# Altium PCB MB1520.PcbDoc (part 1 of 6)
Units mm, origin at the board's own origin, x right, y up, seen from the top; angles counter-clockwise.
Board outline 159 x 88 mm, 6 copper layers (Top Layer, Signal Layer 1, Signal Layer 2, Signal Layer 3, Signal Layer 4, Bottom Layer), stack 1.572 mm thick; 473 components, 377 nets, 1832 pads, 1378 vias.
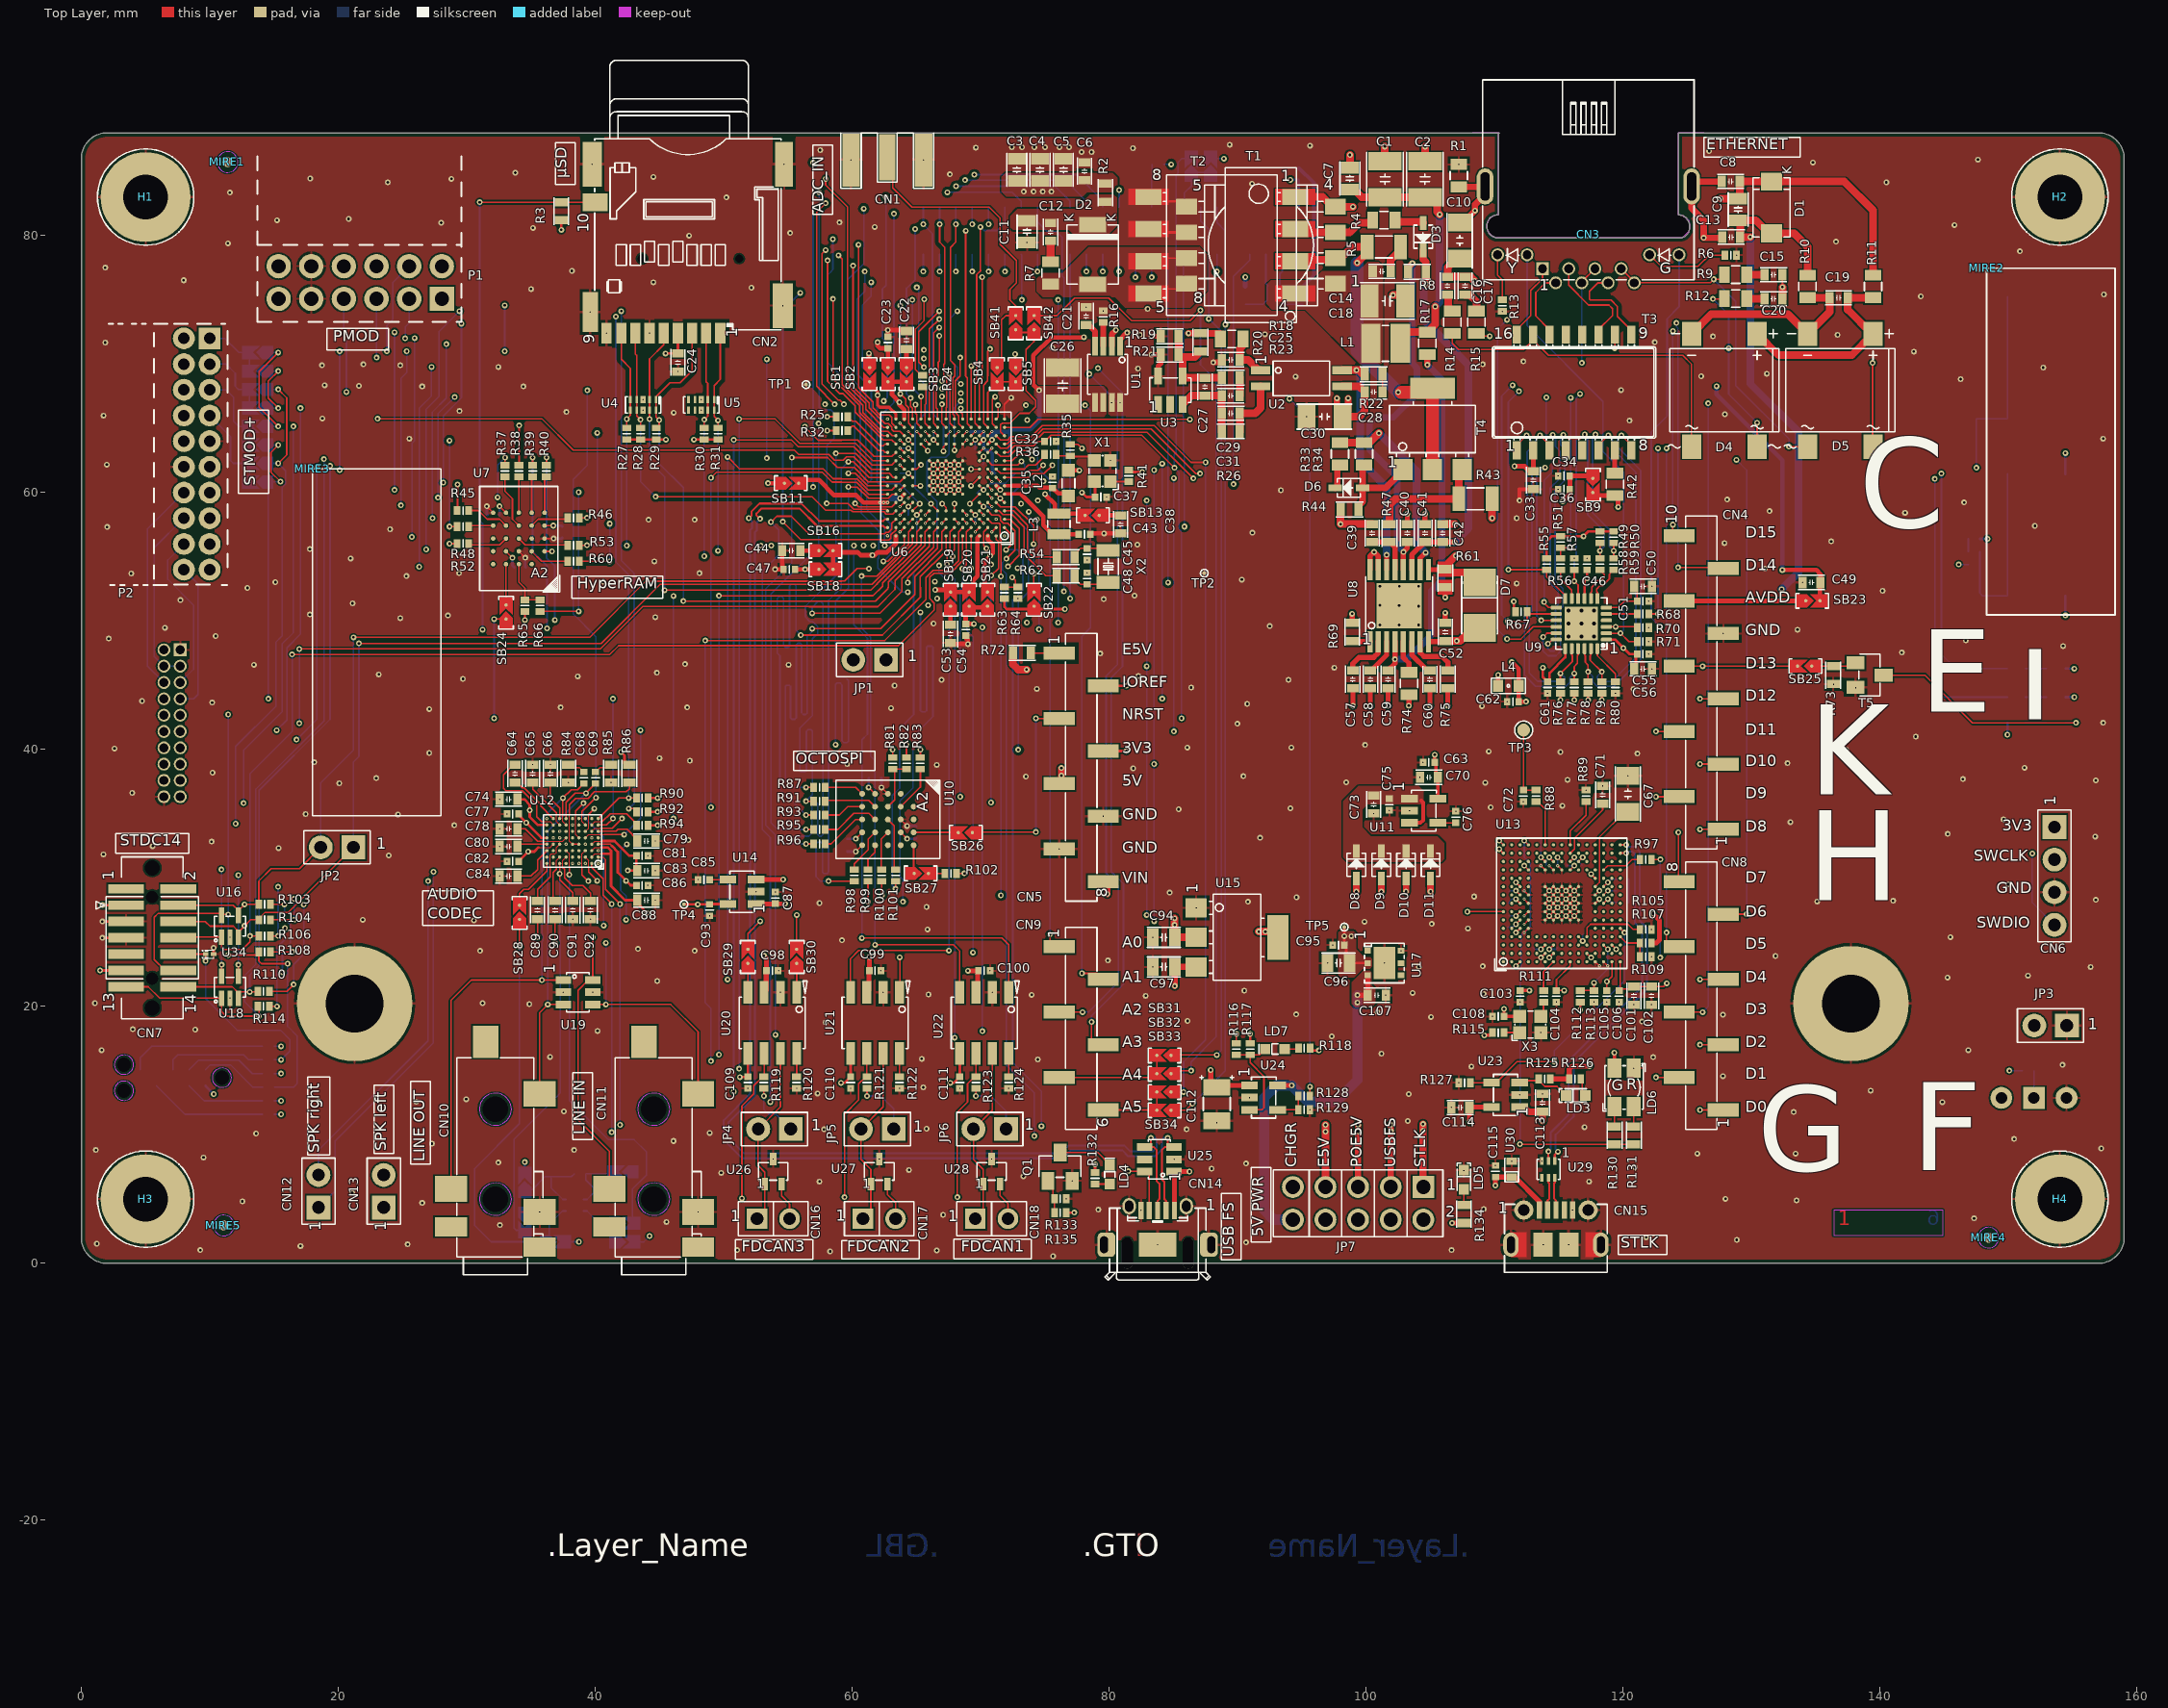
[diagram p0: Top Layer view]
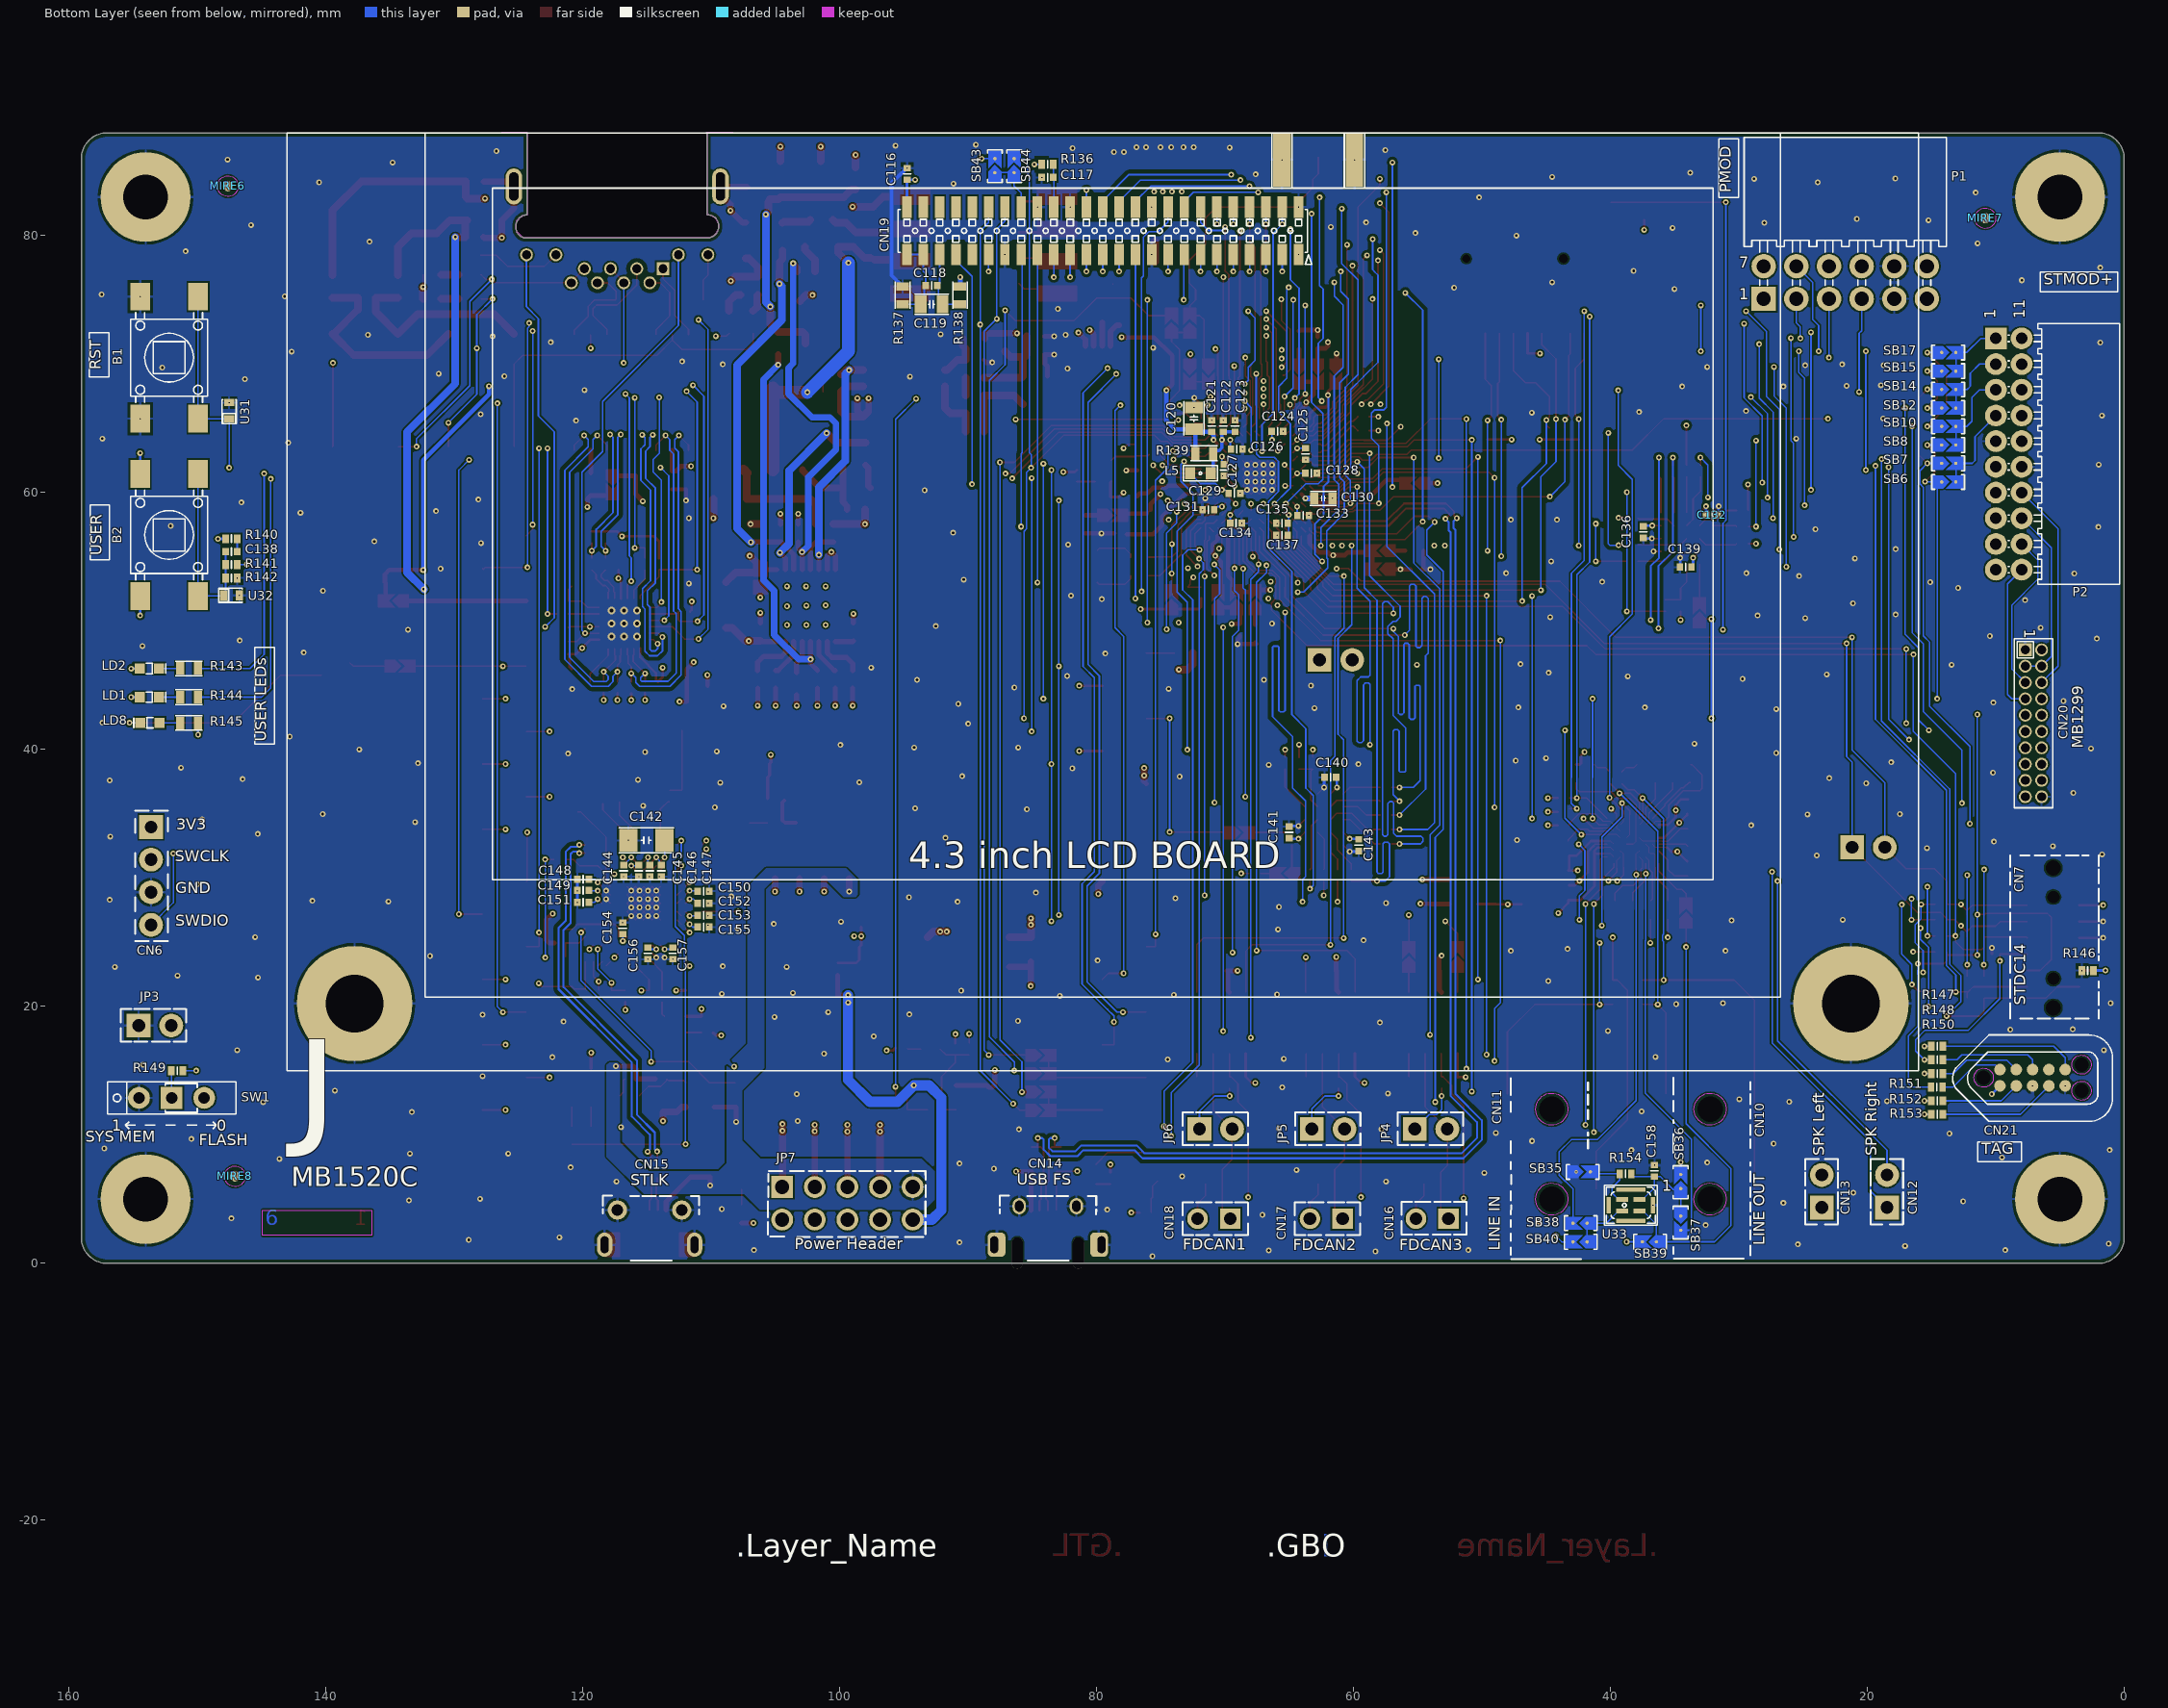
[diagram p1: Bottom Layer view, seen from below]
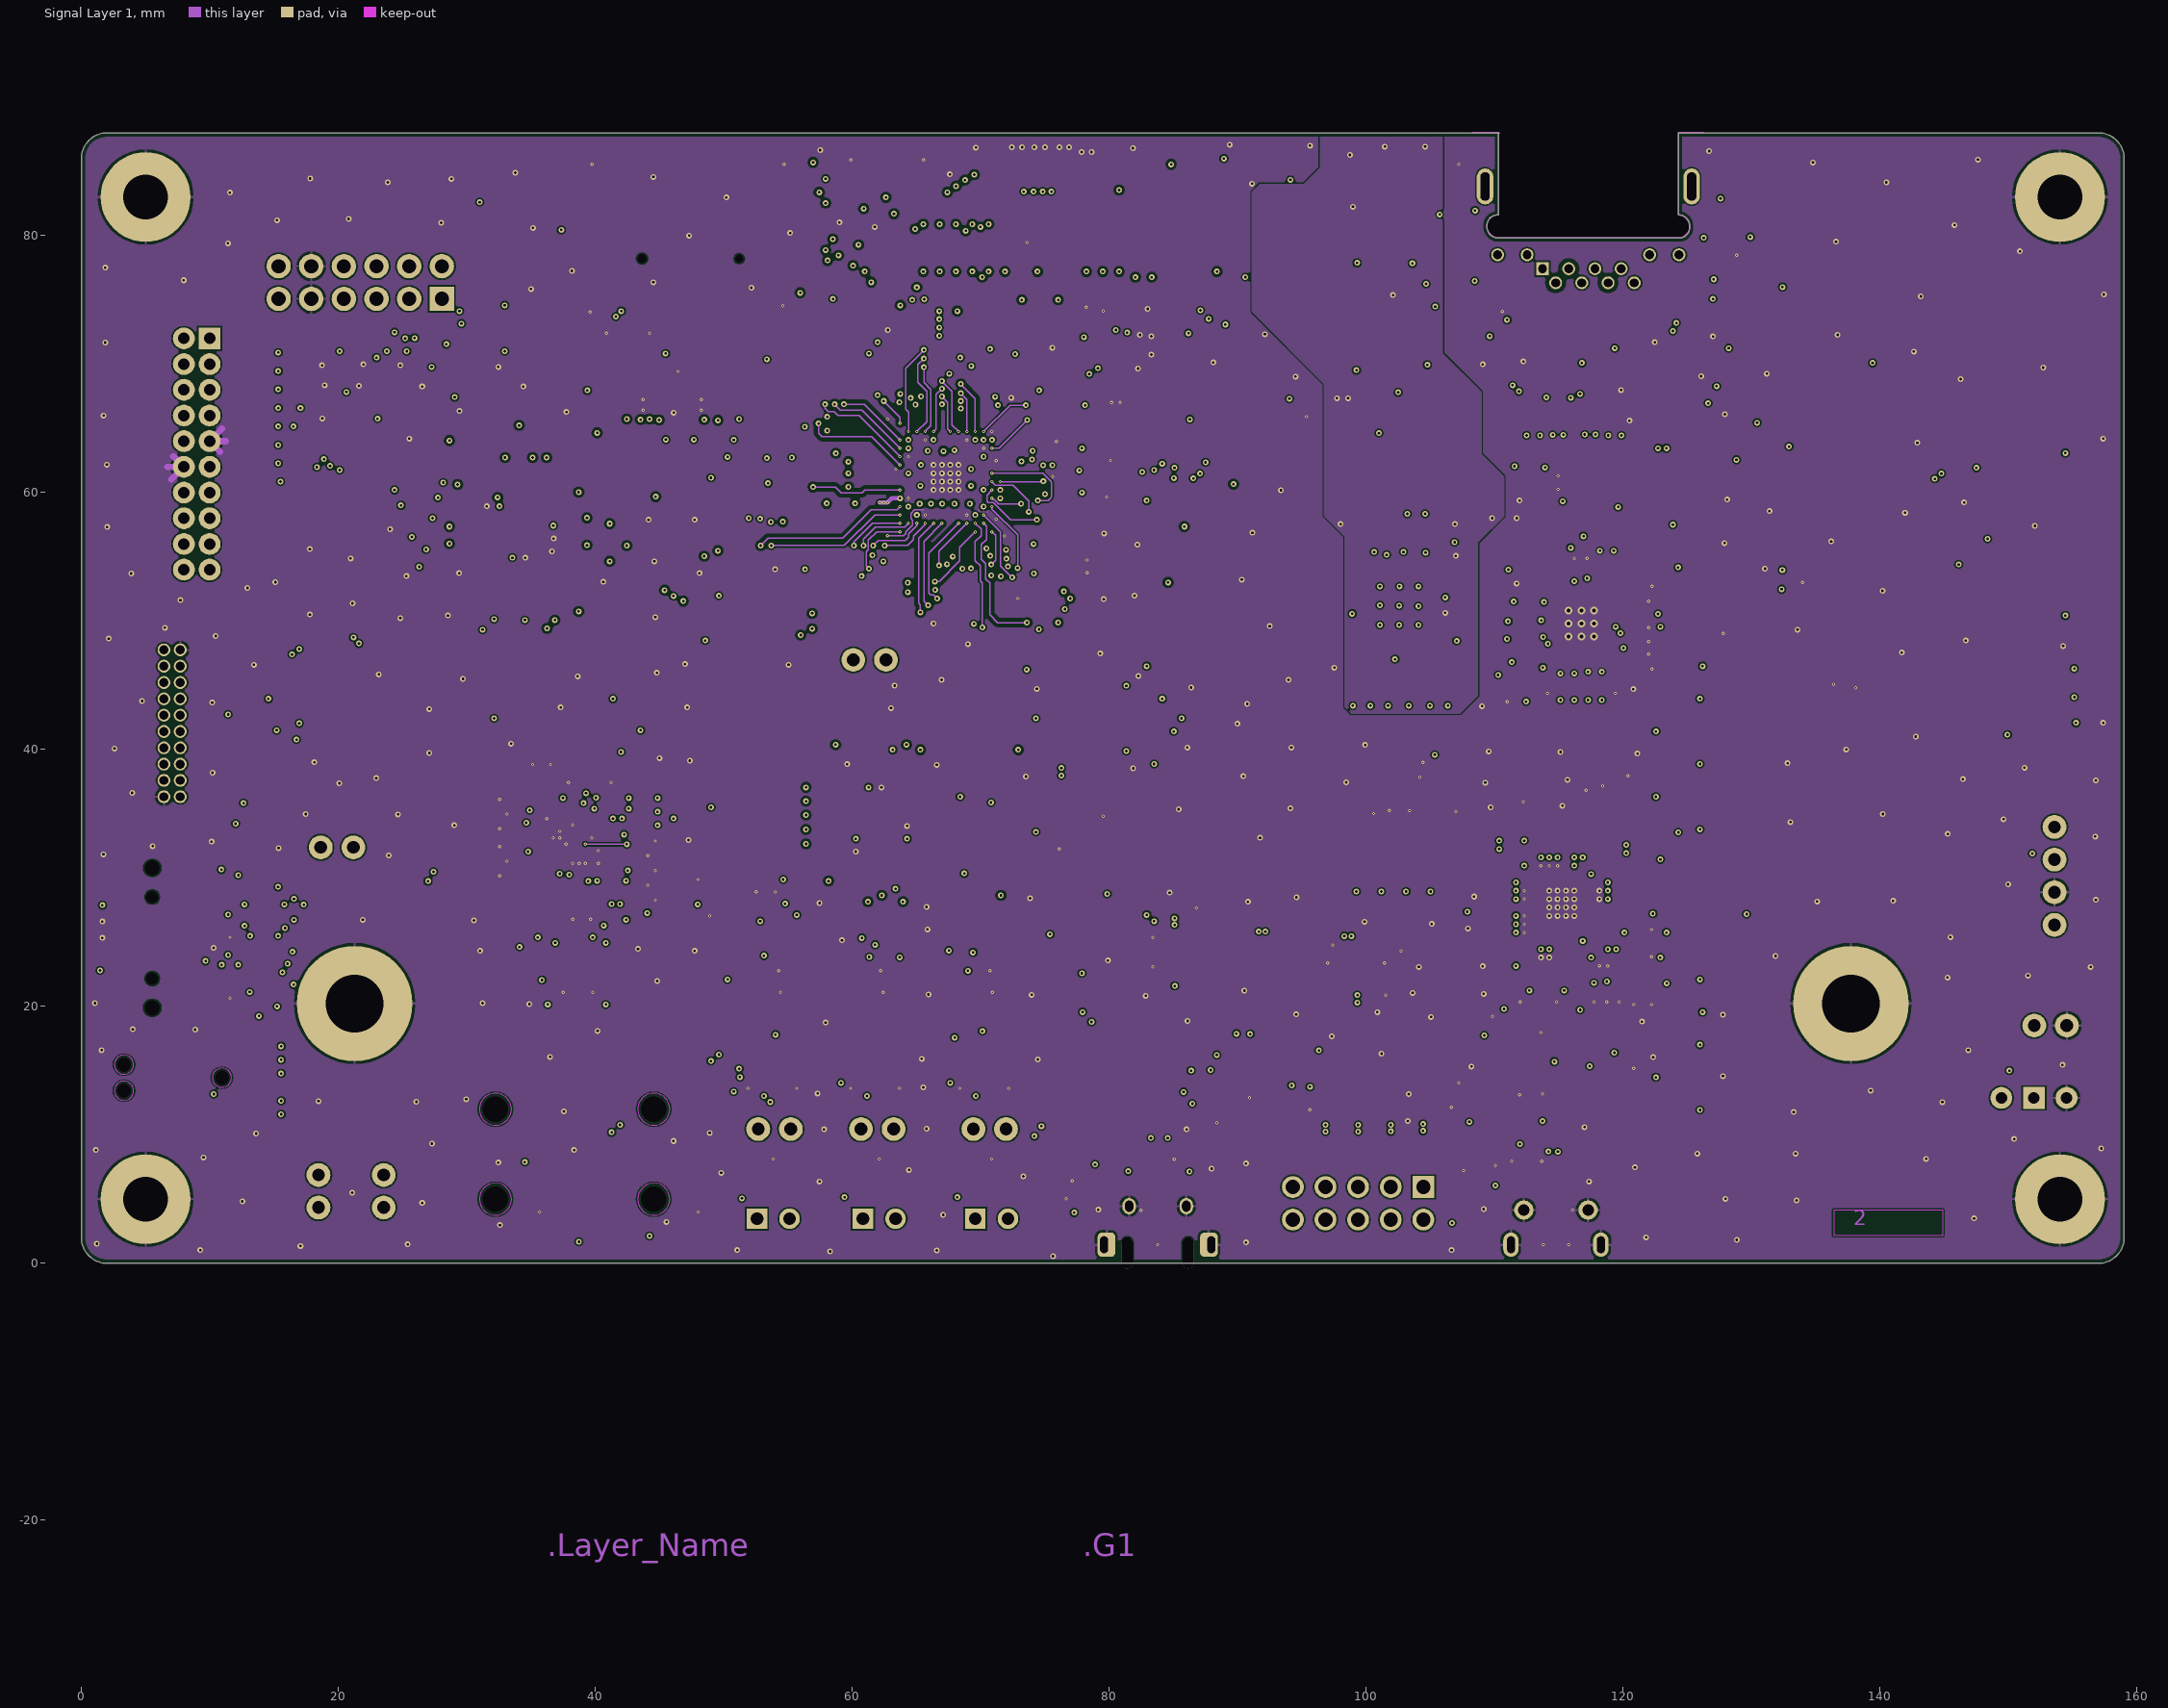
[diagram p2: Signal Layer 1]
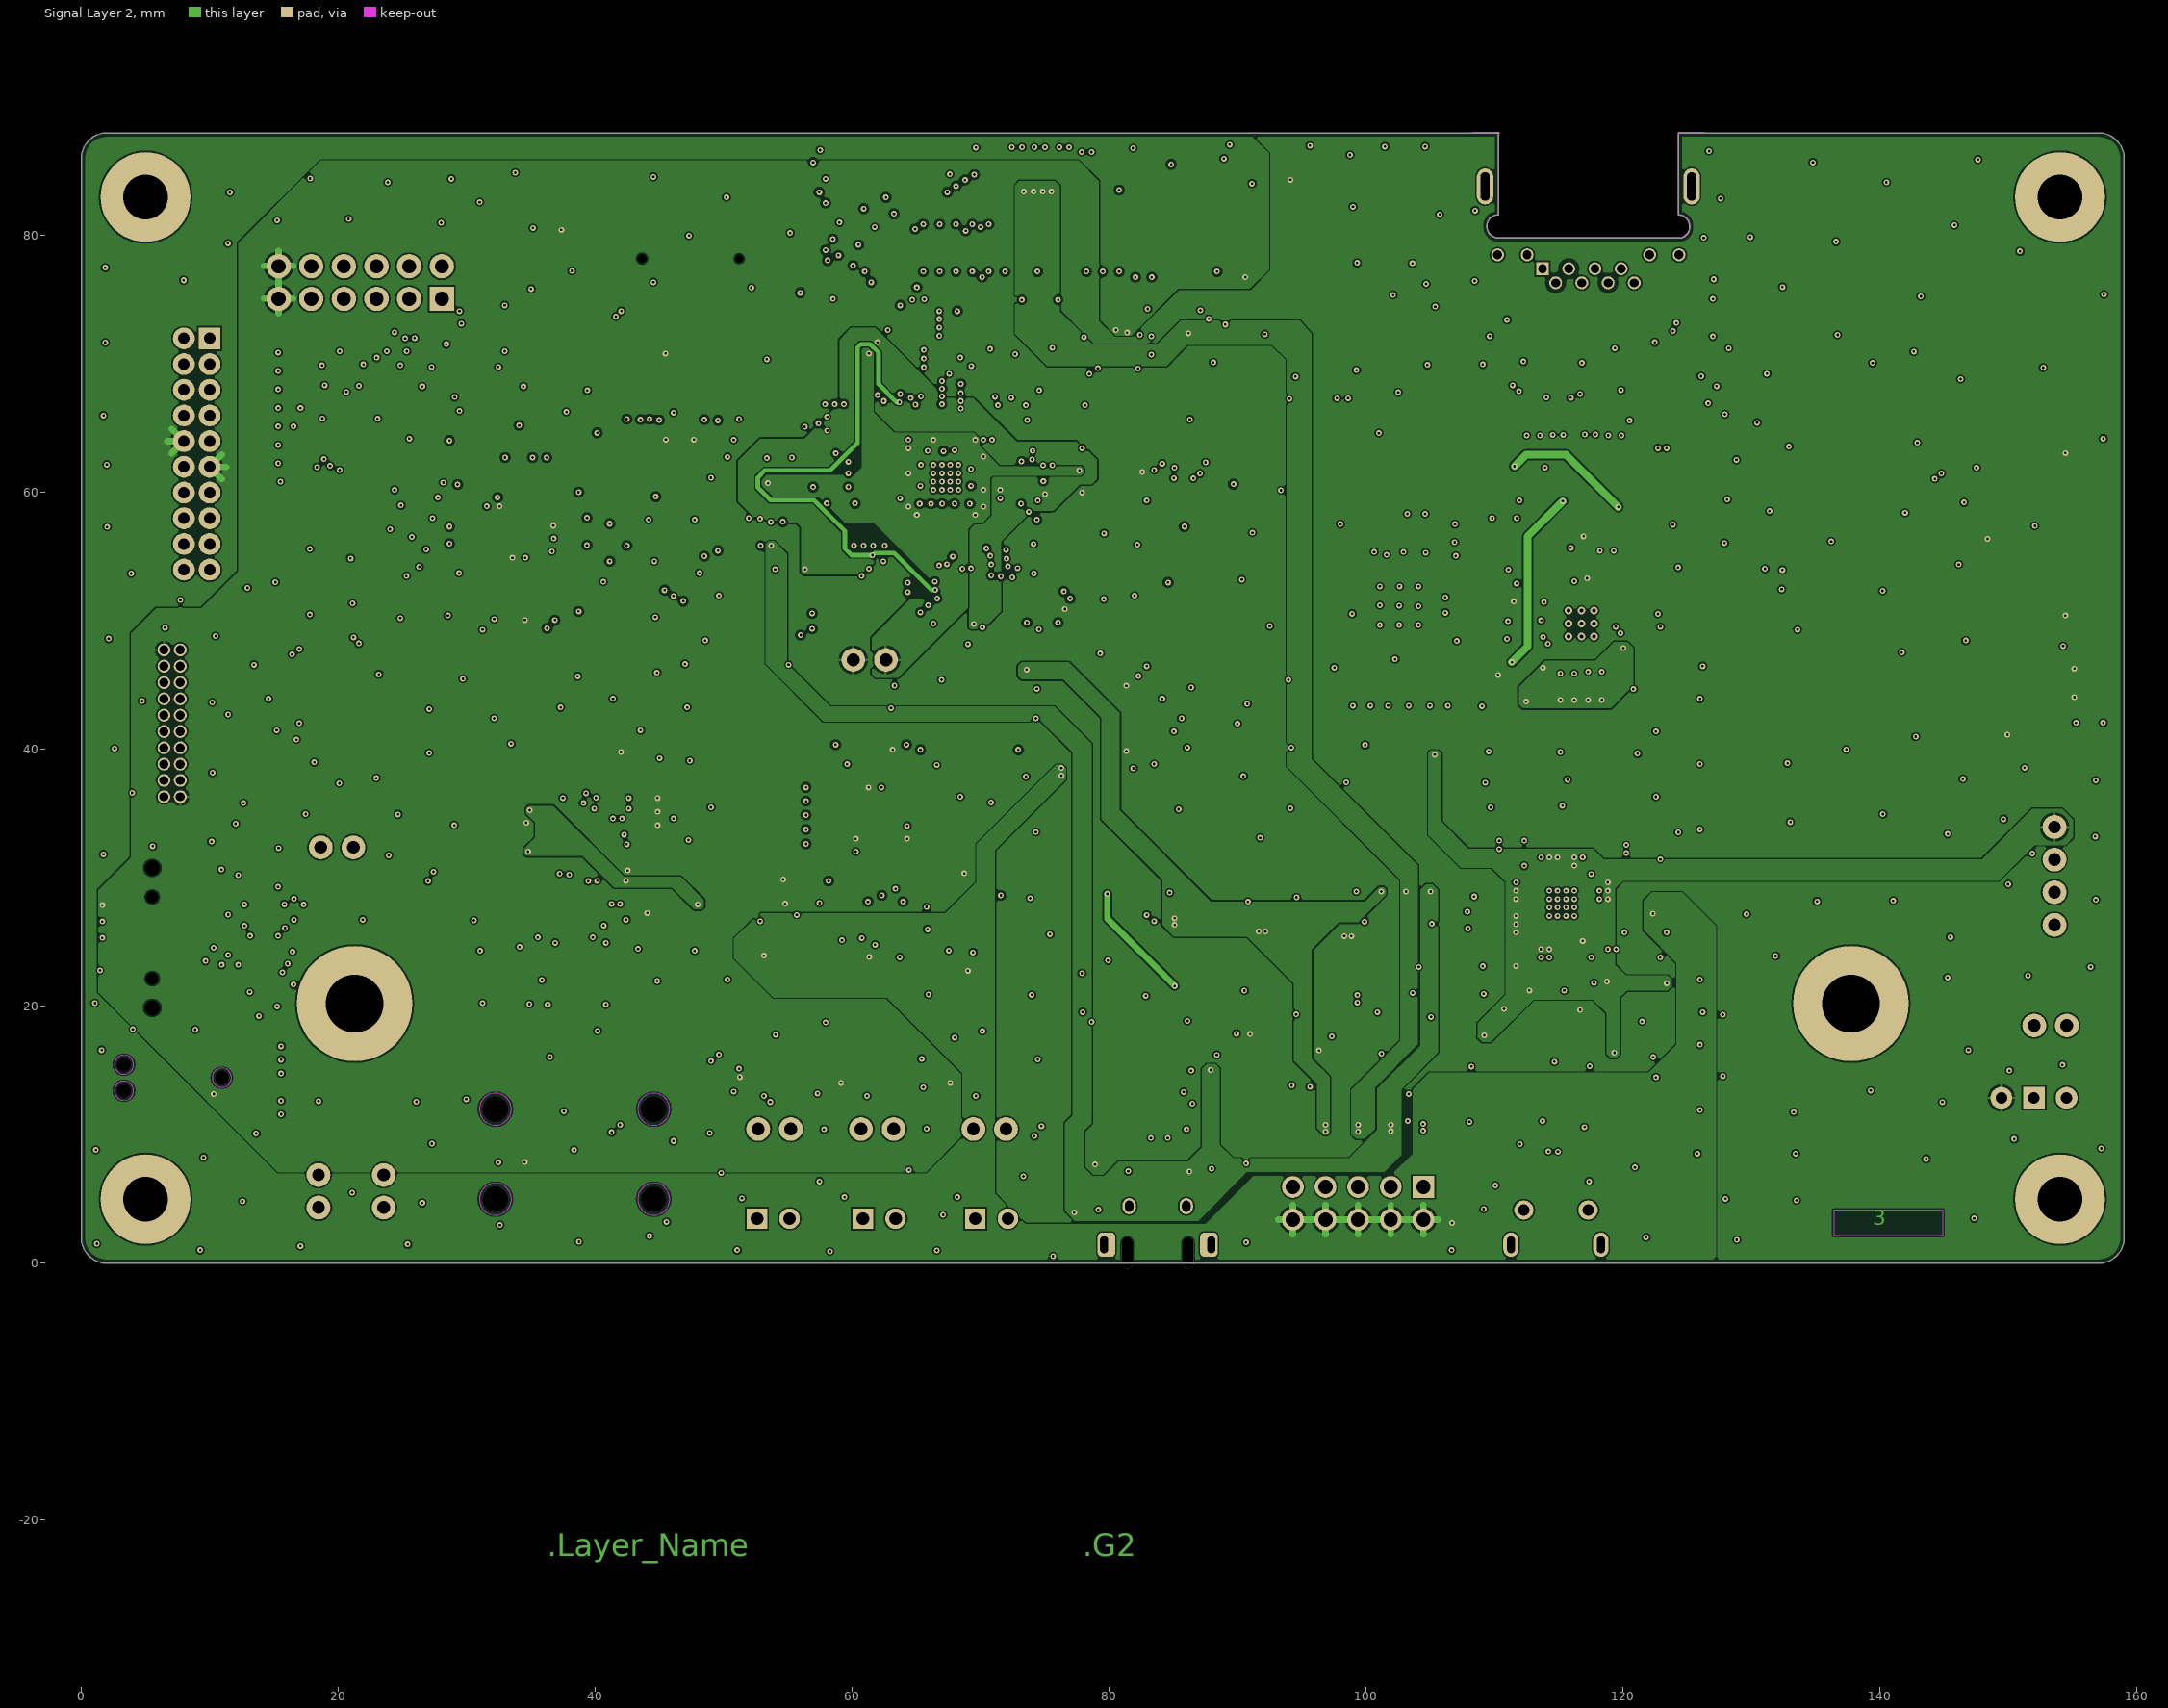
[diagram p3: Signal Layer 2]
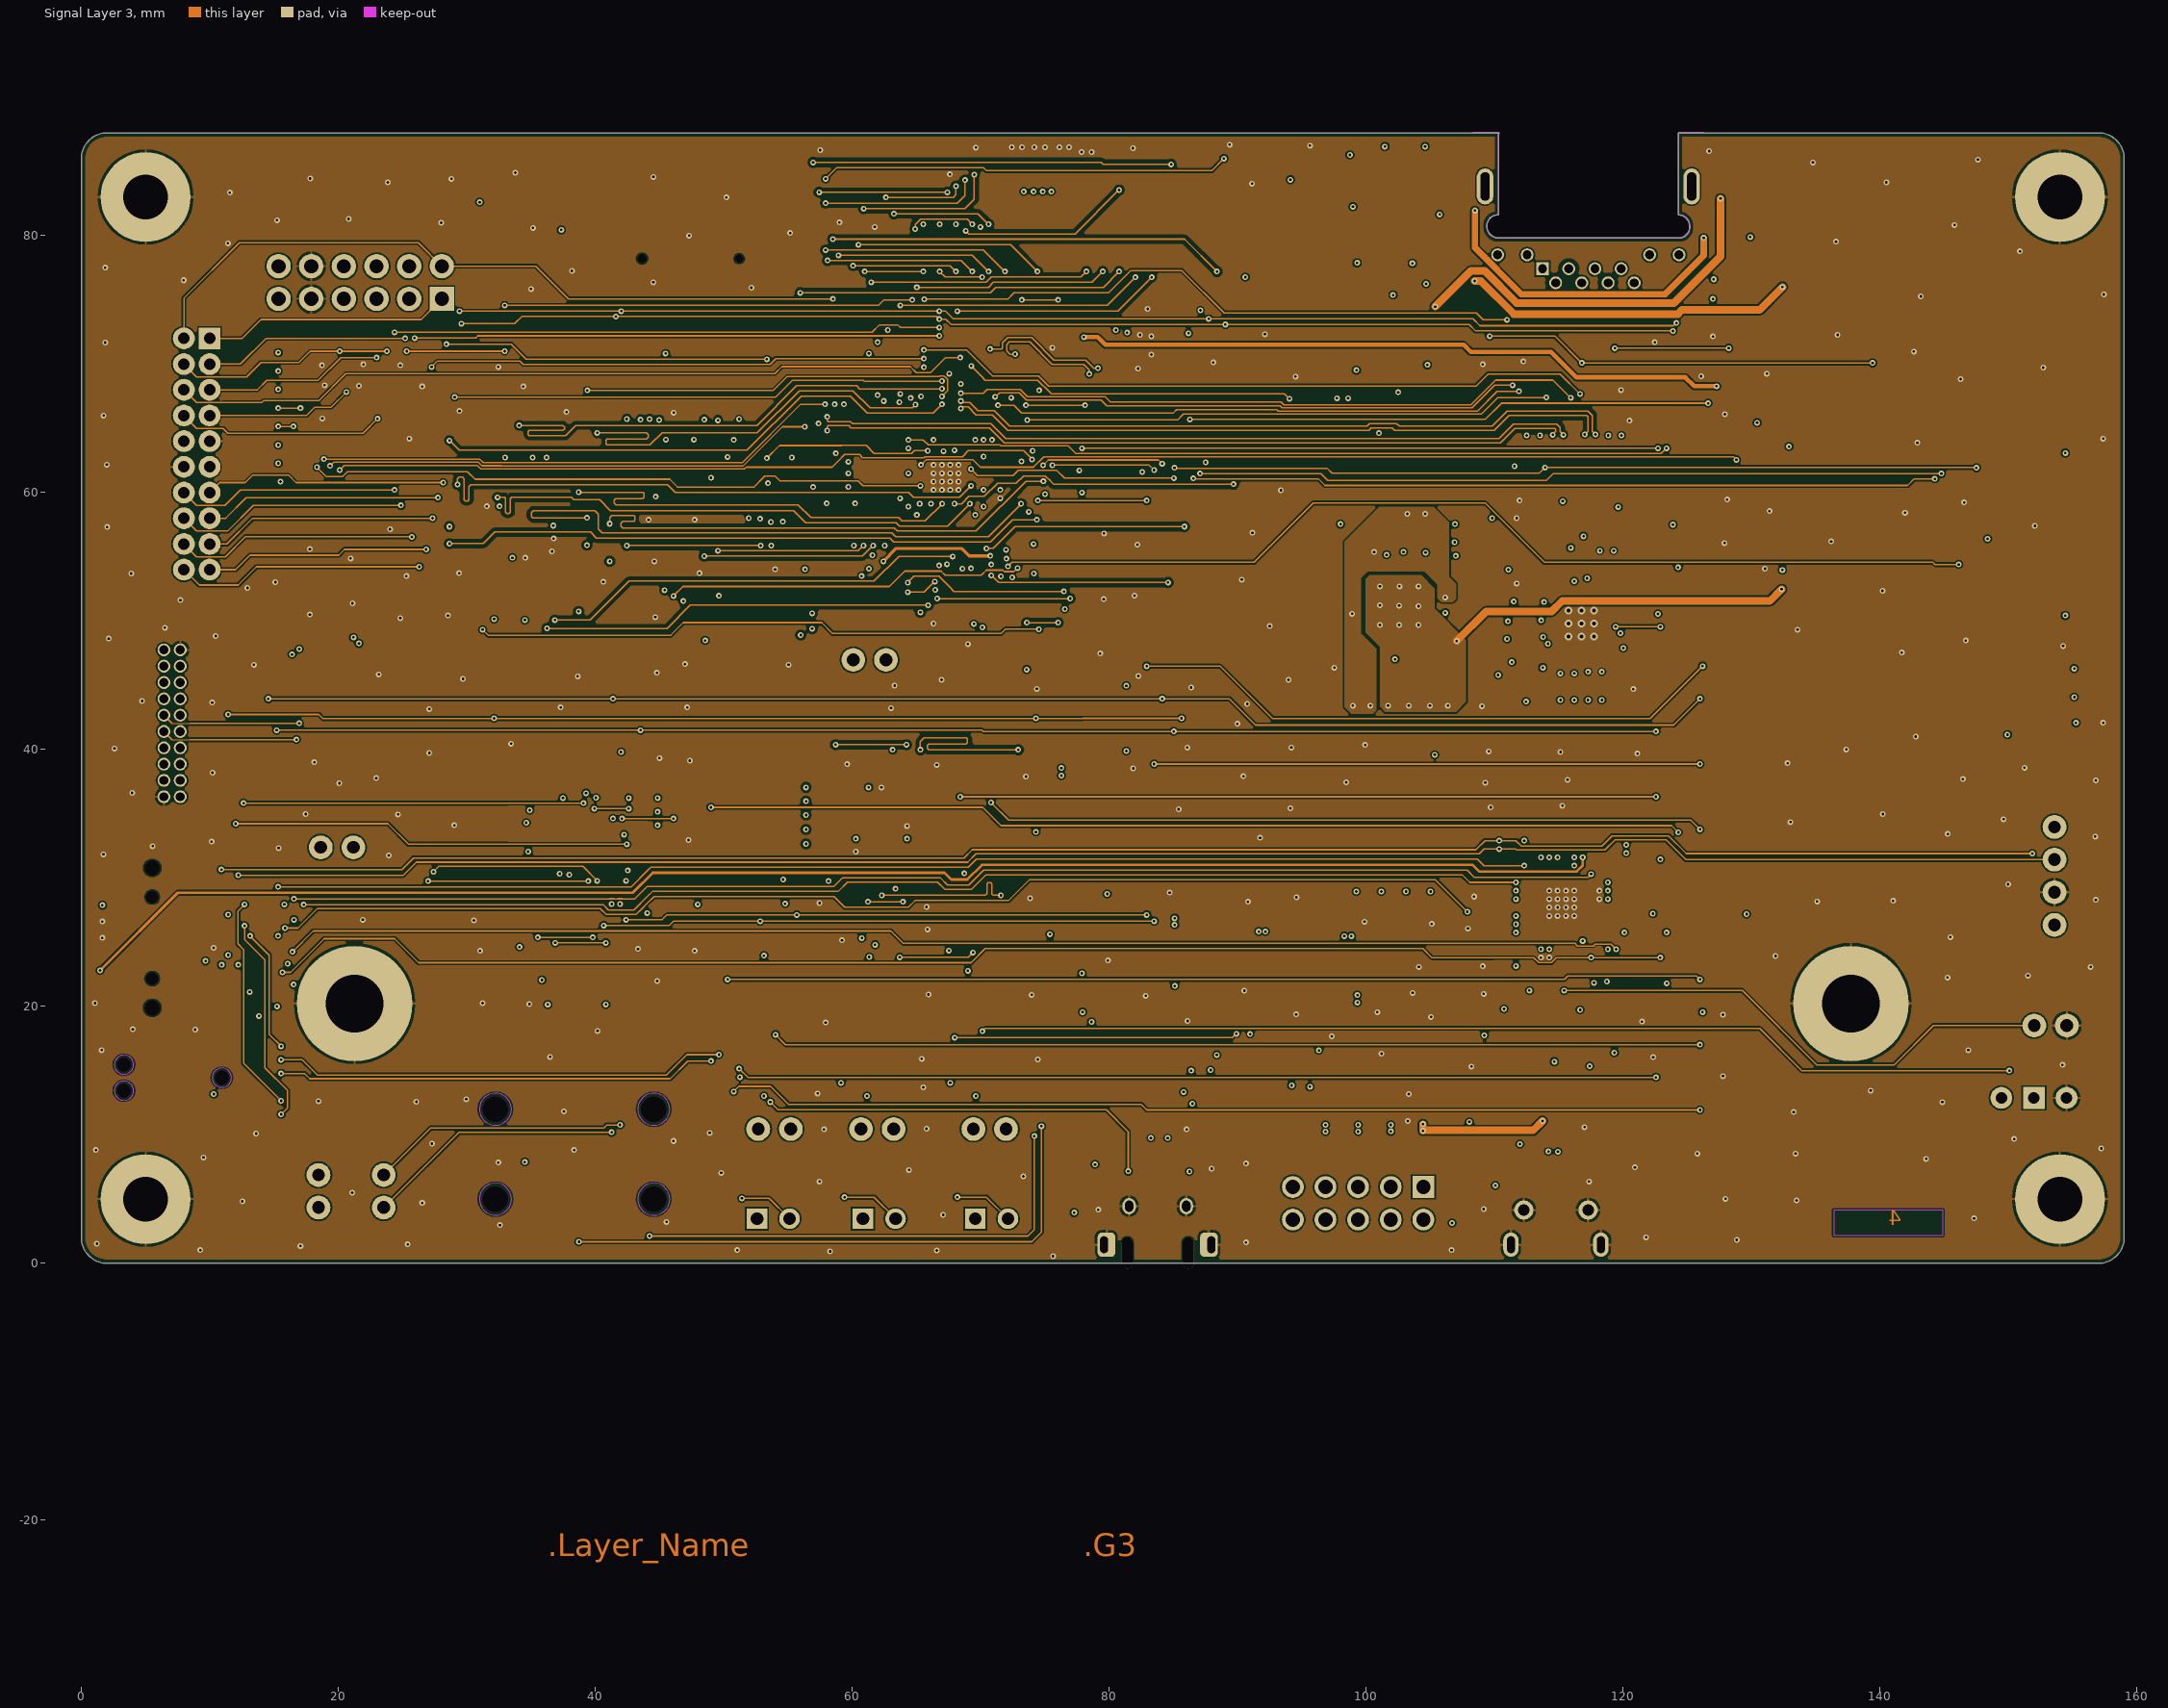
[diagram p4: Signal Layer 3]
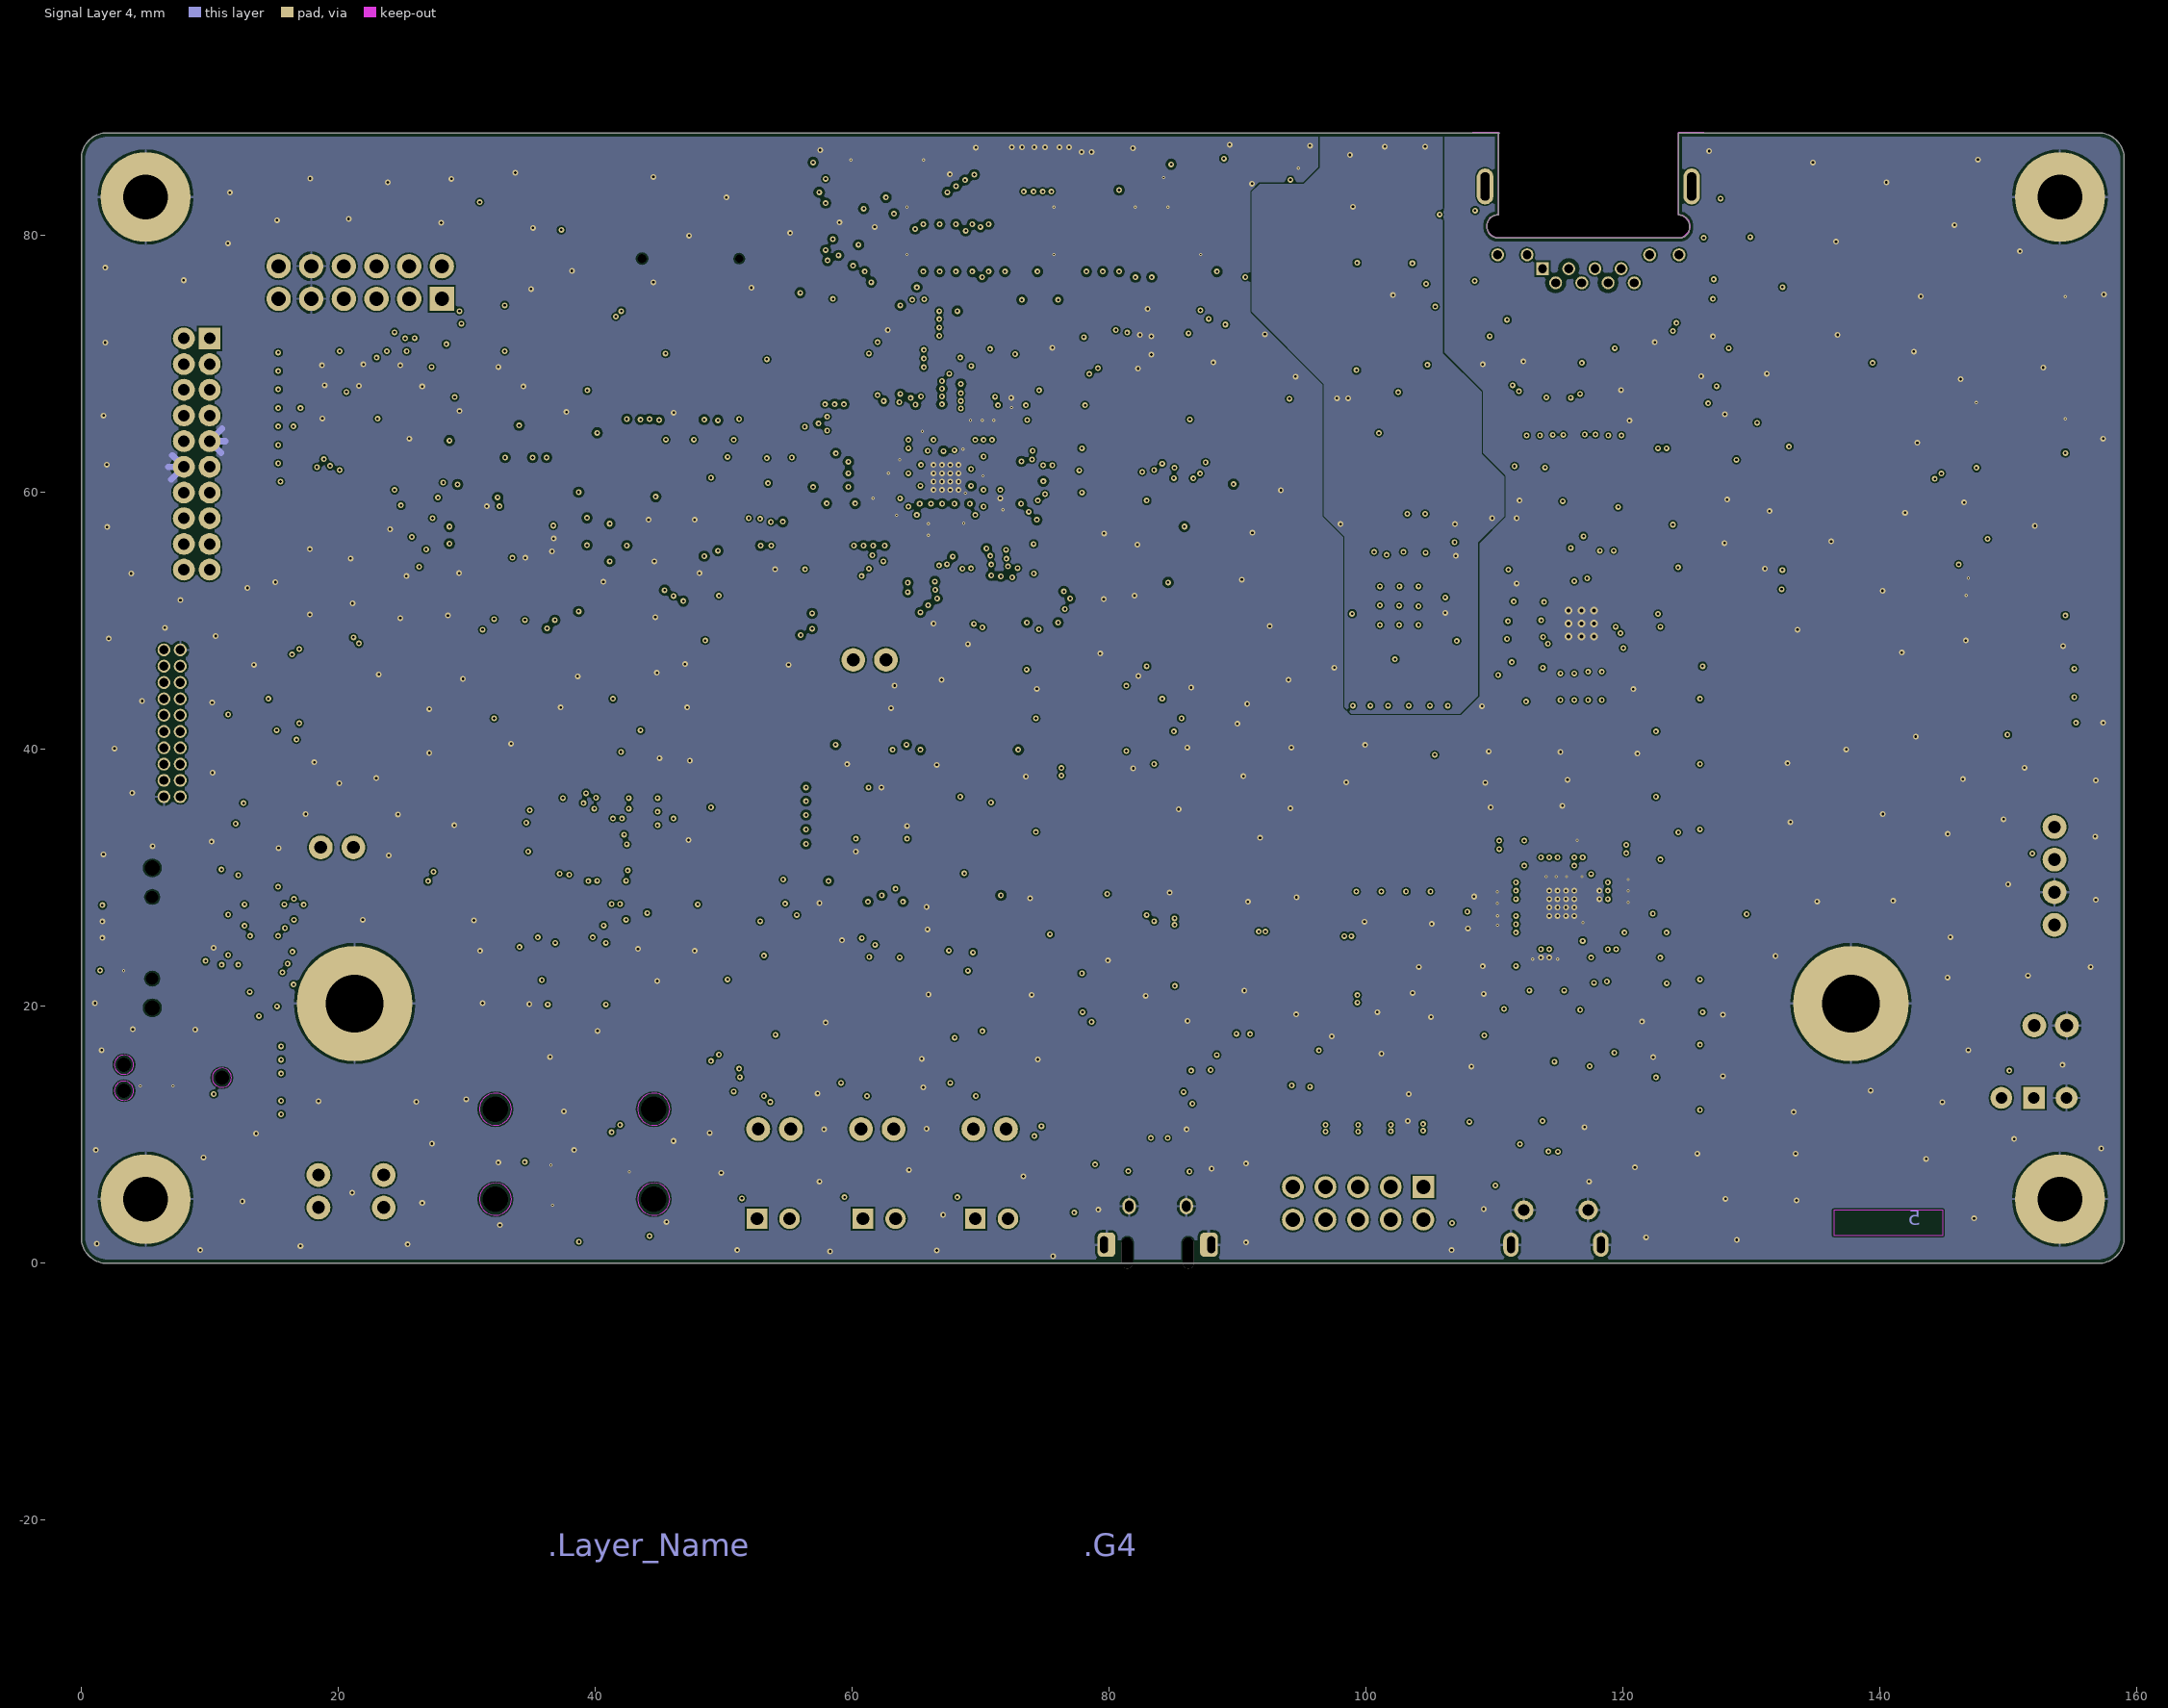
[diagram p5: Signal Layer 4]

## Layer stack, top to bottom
Top Solder: solder mask 0.015, Solder Resist, Dk 3.5
Top Layer: signal copper 0.042
Dielectric1: core 0.099, FR-4, Dk 4.2
Signal Layer 1: signal copper 0.035
Dielectric 2: prepreg 0.102, Dk 4.2
Signal Layer 2: signal copper 0.035
Dielectric 3: core 0.946, FR-4, Dk 4.2
Signal Layer 3: signal copper 0.035
Dielectric 4: prepreg 0.102, Dk 4.2
Signal Layer 4: signal copper 0.035
Dielectric 5: core 0.099, FR-4, Dk 4.2
Bottom Layer: signal copper 0.042
Bottom Solder: solder mask 0.015, Solder Resist, Dk 3.5

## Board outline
0,2 ccw(c2,2) 2,0 157,0 ccw(c157,2) 159,2 159,86 ccw(c157,86) 157,88 124.308,88 124.308,81.61 cw(c124.308,80.742) 125.177,80.742 125.177,80.62 cw(c124.368,80.62) 124.368,79.811 124.303,79.811 110.303,79.811 cw(c110.303,80.71) 109.403,80.71 109.403,80.772 cw(c110.242,80.772) 110.242,81.611 110.303,81.611 110.303,87.936 110.367,88 2,88 ccw(c2,86) 0,86

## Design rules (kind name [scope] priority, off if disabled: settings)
BoardOutlineClearance [All] p1: gap=0.3 ignorepadtopadclearanceinfootprint=FALSE
Clearance Clearance_Diff [InNetClass('Iso_Diff')] p1: gap=0.1 ignorepadtopadclearanceinfootprint=FALSE except(0: Arc-Hole Track-Hole SMDPad-Hole THPad-Hole Via-Hole Fill-Hole Poly-Hole Region-Hole Text-Hole; 0.3: Arc-Fill Arc-Poly Arc-Region Track-Fill Track-Poly Track-Region SMDPad-Fill SMDPad-Poly SMDPad-Region THPad-Fill THPad-Poly THPad-Region Fill-Fill Fill-Poly Fill-Region Poly-Poly Poly-Region Region-Region)
Clearance Clearance_BGA [WithinRoom('RoomDefinition_U6','RoomDefinition_U7','RoomDefinition_U15','RoomDefinition_U16') And TouchesRoom('RoomDefinition_U6','RoomDefinition_U7','RoomDefinition_U15','RoomDefinition_U16') vs OnLayer('Top Layer')] p2: gap=0.1 ignorepadtopadclearanceinfootprint=TRUE except(0: Arc-Hole Track-Hole SMDPad-Hole THPad-Hole Via-Hole Fill-Hole Poly-Hole Region-Hole Text-Hole; 0.08: Track-SMDPad)
Clearance Clearance_300µm [InNetClass('Iso_300µm')] p3: gap=0.12 ignorepadtopadclearanceinfootprint=TRUE except(0: Arc-Hole Track-Hole SMDPad-Hole THPad-Hole Via-Hole Fill-Hole Poly-Hole Region-Hole Text-Hole; 0.2: Via-Fill Via-Poly Via-Region; 0.3: Arc-Arc Arc-Track Arc-Fill Arc-Poly Arc-Region Track-Track Track-Fill Track-Poly Track-Region SMDPad-Fill SMDPad-Poly SMDPad-Region THPad-Fill THPad-Poly THPad-Region Fill-Fill Fill-Poly Fill-Region Poly-Poly Poly-Region Region-Region)
Clearance [All] p4: gap=0.12 ignorepadtopadclearanceinfootprint=FALSE except(0: Arc-Hole Track-Hole SMDPad-Hole THPad-Hole Via-Hole Fill-Hole Poly-Hole Region-Hole Text-Hole)
ComponentClearance [All] p1: gap=0.2 collisioncheckmode=3 verticalgap=0.2 showdistances=FALSE
DiffPairsRouting DiffPairsRouting_100ohms [InDifferentialPairClass('100ohms')] p1: maxlimit=0.254 minlimit=0.227 mostfreqgap=0.254 toplayer_mingap=0.251 toplayer_maxgap=0.251 toplayer_prefgap=0.251 toplayer_minwidth=0.13 toplayer_maxwidth=0.13 toplayer_prefwidth=0.13 midlayer1_mingap=0.254 midlayer1_minwidth=0.381 midlayer1_maxwidth=0.381 midlayer1_prefwidth=0.381 midlayer2_mingap=0.254 midlayer2_minwidth=0.381 midlayer2_maxwidth=0.381 midlayer2_prefwidth=0.381 midlayer3_maxgap=0.227 midlayer3_prefgap=0.227 midlayer3_minwidth=0.104 midlayer3_maxwidth=0.104 midlayer3_prefwidth=0.104 midlayer4_mingap=0.254 midlayer4_minwidth=0.381 midlayer4_maxwidth=0.381 midlayer4_prefwidth=0.381 bottomlayer_mingap=0.251 bottomlayer_maxgap=0.251 bottomlayer_prefgap=0.251 bottomlayer_minwidth=0.13 bottomlayer_maxwidth=0.13 bottomlayer_prefwidth=0.13 maxuncoupledlength=12.7
DiffPairsRouting DiffPairsRouting_90ohms [InDifferentialPairClass('90ohms')] p2: maxlimit=0.254 minlimit=0.226 mostfreqgap=0.254 toplayer_maxgap=0.226 toplayer_prefgap=0.226 toplayer_minwidth=0.155 toplayer_maxwidth=0.155 toplayer_prefwidth=0.155 midlayer1_mingap=0.254 midlayer1_minwidth=0.381 midlayer1_maxwidth=0.381 midlayer1_prefwidth=0.381 midlayer2_mingap=0.254 midlayer2_minwidth=0.381 midlayer2_maxwidth=0.381 midlayer2_prefwidth=0.381 midlayer3_mingap=0.251 midlayer3_maxgap=0.251 midlayer3_prefgap=0.251 midlayer3_minwidth=0.13 midlayer3_maxwidth=0.13 midlayer3_prefwidth=0.13 midlayer4_mingap=0.254 midlayer4_minwidth=0.381 midlayer4_maxwidth=0.381 midlayer4_prefwidth=0.381 bottomlayer_maxgap=0.226 bottomlayer_prefgap=0.226 bottomlayer_minwidth=0.155 bottomlayer_maxwidth=0.155 bottomlayer_prefwidth=0.155 maxuncoupledlength=12.7
HoleSize [All] p1: absolutevalues=TRUE maxlimit=10 minlimit=0.025 maxpercent=80.000 minpercent=20.000
MatchedLengths MatchedLengths_OctoSPI [InNetClass('OctoSPI')] p1: tolerance=7 checknetsindiffpair=FALSE checkdiffpairvsdiffpair=TRUE checkxsignals=TRUE checkothers=TRUE
MatchedLengths MatchedLengths_HyperRAM [InNetClass('HyperRAM')] p2: tolerance=7 checknetsindiffpair=FALSE checkdiffpairvsdiffpair=TRUE checkxsignals=TRUE checkothers=TRUE
MaxMinImpedance "Schematic Impedance Constraint_3" [InNet('USB_DEV_HS_P')] p1: minimum=85,00 maximum=95,00
MaxMinImpedance "Schematic Impedance Constraint_2" [InNet('USB_DEV_HS_CN_P')] p2: minimum=85,00 maximum=95,00
MaxMinImpedance "Schematic Impedance Constraint_1" [InNet('USB_DEV_HS_N')] p3: minimum=85,00 maximum=95,00
MaxMinImpedance "Schematic Impedance Constraint" [InNet('USB_DEV_HS_CN_N')] p4: minimum=85,00 maximum=95,00
MinimumSolderMaskSliver [All] p1: minsoldermaskwidth=0.013
PlaneClearance [All] p1: clearance=0.3
PlaneConnect [All] p1: planeconnectstyle=Relief reliefexpansion=0.508 reliefentries=4 reliefconductorwidth=0.254 reliefairgap=0.152
PolygonConnect PolygonConnect_NO_TH [IsNamedPolygon('NO_TH')] p1: connectstyle=Direct reliefconductorwidth=0.254 reliefentries=4 polygonreliefangle="90 Angle" airgapwidth=0.254
PolygonConnect [All] p2: thpad.connectstyle=Relief thpad.reliefconductorwidth=0.2 thpad.reliefentries=4 thpad.polygonreliefangle="90 Angle" thpad.airgapwidth=0.2 smdpad.connectstyle=Relief smdpad.reliefconductorwidth=0.2 smdpad.reliefentries=4 smdpad.polygonreliefangle="90 Angle" smdpad.airgapwidth=0.2 via.connectstyle=Direct via.reliefconductorwidth=0.508 via.reliefentries=4 via.polygonreliefangle="90 Angle" via.airgapwidth=0.152
RoomDefinition RoomDefinition_U16 [InComponentClass('Room Definition 1')] p1: confinementstyle=ConfineIn formatcopy=TRUE lockcomponents=FALSE outline 109.908,22.702 109.908,33.352 120.558,33.352 120.558,22.702
RoomDefinition RoomDefinition_U15 [InComponentClass('Room Definition 1')] p2: confinementstyle=ConfineIn formatcopy=TRUE lockcomponents=FALSE outline 44.1,27.5 33.2,27.5 33.2,37.8 44.1,37.8
RoomDefinition RoomDefinition_U7 [InComponentClass('Room Definition 1')] p3: confinementstyle=ConfineIn formatcopy=TRUE lockcomponents=FALSE outline 29.7,50.825 29.7,61.725 38.325,61.725 38.325,50.825
RoomDefinition RoomDefinition_U6 [InComponentClass('Room Definition 1')] p4: confinementstyle=ConfineIn formatcopy=TRUE lockcomponents=FALSE outline 59.175,52.625 59.175,69.075 75.425,69.075 75.425,52.625
RoutingVias [All] p1: holewidth=0.2 width=0.45 viastyle="Through Hole" minholewidth=0.1 minwidth=0.25 maxholewidth=0.2 maxwidth=0.45
SilkToSilkClearance STM32_LOGO [(ObjectKind = 'Text') And (Component = 'HW10')] p1: silktosilkclearance=0
SilkToSilkClearance LOGO [(ObjectKind = 'Text') And (Component = 'HW2')] p2: silktosilkclearance=0
SilkToSilkClearance [All] p3: silktosilkclearance=0.102
SilkToSolderMaskClearance [IsPad] p1: minsilkscreentomaskgap=0.008 clearancetoexposedcopper=TRUE
SolderMaskExpansion [All] p1: expansion=0.102 istentingtop=FALSE
Width Width_Alim [InNetClass('Alim')] p1: maxlimit=2 minlimit=0.1 preferedwidth=0.2
Width Width_BGA [WithinRoom('RoomDefinition_U6','RoomDefinition_U7','RoomDefinition_U15','RoomDefinition_U16') and TouchesRoom('RoomDefinition_U6','RoomDefinition_U7','RoomDefinition_U15','RoomDefinition_U16')] p2: maxlimit=1 minlimit=0.09 preferedwidth=0.1 minimp=50.000000 maximp=50.000000 favimp=50.000000
Width Width_55Ohms [InNetClass('55 Ohms')] p3: maxlimit=0.254 minlimit=0.1 preferedwidth=0.254 toplayer_minwidth=0.127 toplayer_maxwidth=0.127 toplayer_prefwidth=0.127 midlayer3_minwidth=0.102 midlayer3_maxwidth=0.102 midlayer3_prefwidth=0.102 bottomlayer_minwidth=0.127 bottomlayer_maxwidth=0.127 bottomlayer_prefwidth=0.127 minimp=50.000000 maximp=50.000000 favimp=50.000000
Width [All] p4: maxlimit=1 minlimit=0.12 preferedwidth=0.12 minimp=50.000000 maximp=50.000000 favimp=50.000000
22 further rules are at their usual default settings.

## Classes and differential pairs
net class OctoSPI: NetR24_2 NetR82_1 NetR83_2 NetR87_1 NetR91_1 NetR93_1 NetR95_1 NetR96_1 NetR98_1 NetR99_1 NetR100_2
net class Iso_300µm: CTP_INT LCD_B0 LCD_B1 LCD_B2 LCD_B3 LCD_B4 LCD_B5 LCD_B6 LCD_B7 LCD_BL_CTRL LCD_CLK LCD_DE LCD_DISP LCD_G0 LCD_G1 LCD_G2 LCD_G3 LCD_G4 LCD_G5 LCD_G6 LCD_G7 LCD_HSYNC LCD_R0 LCD_R1 LCD_R2 LCD_R3 LCD_R4 LCD_R5 LCD_R6 LCD_R7 LCD_VSYNC NetR24_2 NetR37_2 NetR38_1 NetR39_1 NetR40_1 NetR45_2 NetR46_2 NetR48_1 NetR52_2 NetR53_2 NetR60_2 NetR66_1 NetR82_1 NetR83_2 NetR87_1 NetR91_1 NetR93_1 NetR95_1 NetR96_1 NetR98_1 NetR99_1 NetR100_2 OCSPI1_CLK OCSPI1_DQS OCSPI1_IO0 OCSPI1_IO1 OCSPI1_IO2 OCSPI1_IO3 OCSPI1_IO4 OCSPI1_IO5 OCSPI1_IO6 OCSPI1_IO7 OCSPI1_NCS OCSPI2_CLK OCSPI2_DQS OCSPI2_IO0 OCSPI2_IO1 OCSPI2_IO2 OCSPI2_IO3 OCSPI2_IO4 OCSPI2_IO5 OCSPI2_IO6 OCSPI2_IO7 OCSPI2_NCS SDIO1_CK SDIO1_CMD SDIO1_D0 SDIO1_D1 SDIO1_D2 SDIO1_D3
differential pair class 100ohms: ARD_A RD RD_CN RMII_RXD RMII_RXD_R RMII_TXD RMII_TXD_R TD TD_CN
differential pair class 90ohms: USB_DEV_HS USB_DEV_HS_CN USB_FS
net class LCD: CTP_INT LCD_B0 LCD_B1 LCD_B2 LCD_B3 LCD_B4 LCD_B5 LCD_B6 LCD_B7 LCD_BL_CTRL LCD_CLK LCD_DE LCD_DISP LCD_G0 LCD_G1 LCD_G2 LCD_G3 LCD_G4 LCD_G5 LCD_G6 LCD_G7 LCD_HSYNC LCD_R0 LCD_R1 LCD_R2 LCD_R3 LCD_R4 LCD_R5 LCD_R6 LCD_R7 LCD_VSYNC
net class HyperRAM_R: OCSPI2_CLK OCSPI2_DQS OCSPI2_IO0 OCSPI2_IO1 OCSPI2_IO2 OCSPI2_IO3 OCSPI2_IO4 OCSPI2_IO5 OCSPI2_IO6 OCSPI2_IO7 OCSPI2_NCS
net class OctoSPI_R: OCSPI1_CLK OCSPI1_DQS OCSPI1_IO0 OCSPI1_IO1 OCSPI1_IO2 OCSPI1_IO3 OCSPI1_IO4 OCSPI1_IO5 OCSPI1_IO6 OCSPI1_IO7 OCSPI1_NCS
net class SD_CARD: SDIO1_CK SDIO1_CMD SDIO1_D0 SDIO1_D1 SDIO1_D2 SDIO1_D3
net class "55 Ohms": ADC_IN LCD_B0 LCD_B1 LCD_B2 LCD_B3 LCD_B4 LCD_B5 LCD_B6 LCD_B7 LCD_CLK LCD_DE LCD_G0 LCD_G1 LCD_G2 LCD_G3 LCD_G4 LCD_G5 LCD_G6 LCD_G7 LCD_HSYNC LCD_R0 LCD_R1 LCD_R2 LCD_R3 LCD_R4 LCD_R5 LCD_R6 LCD_R7 LCD_VSYNC NetR24_2 NetR35_2 NetR36_2 NetR37_2 NetR38_1 NetR39_1 NetR40_1 NetR45_2 NetR46_2 NetR48_1 NetR52_2 NetR53_2 NetR60_2 NetR66_1 NetR82_1 NetR83_2 NetR87_1 NetR91_1 NetR93_1 NetR95_1 NetR96_1 NetR98_1 NetR99_1 NetR100_2 OCSPI1_CLK OCSPI1_DQS OCSPI1_IO0 OCSPI1_IO1 OCSPI1_IO2 OCSPI1_IO3 OCSPI1_IO4 OCSPI1_IO5 OCSPI1_IO6 OCSPI1_IO7 OCSPI1_NCS OCSPI2_CLK OCSPI2_DQS OCSPI2_IO0 OCSPI2_IO1 OCSPI2_IO2 OCSPI2_IO3 OCSPI2_IO4 OCSPI2_IO5 OCSPI2_IO6 OCSPI2_IO7 OCSPI2_NCS OSC_25M RMII_REF_CLK SDIO1_CK SDIO1_CMD SDIO1_D0 SDIO1_D1 SDIO1_D2 SDIO1_D3
component class "Components Class 1": C52 C73 C119 C120 C121 C122 C123 C127 C128 C129 C131 C133 C134 C151 L4 R139 U6
component class "U_SD CARD": C52 CN2 R3 R14 R27 R29 R30 R31 U4 U5
component class U_LCD: C97 C119 C151 C155 CN19 HW2 R136 R137 R138
component class Audio: C24 C46 C48 C52 C53 C55 C57 C64 C65 C66 C68 C79 C81 C82 C84 C91 C92 C128 C132 C137 C151 CN15 CN17 CN18 CN21 R67 R71 R84 R85 R86 R90 R154 SB30 SB31 SB34 SB37 SB38 SB39 SB40 U12 U19 U33
component class Arduino: C52 CN5 CN8 CN17 LD8 R72 R73 R103 SB25 SB27 SB31 SB32 SB33 SB34 T5
component class U_Ethernet: C40 C52 C57 C58 C62 C142 L4 R6 R11 R41 R46 R49 R51 R55 R56 R57 R58 R59 R67 R68 R70 R71 R77 R78 R79 R80 U300
component class U_OCSPI: C140 C142 C144 R82 R102 SB26 SB27 U10
component class FDCANs: C65 C98 C99 C109 C111 C131 CN15 CN17 CN21 JP4 JP5 JP6 R68 R70 R120 R121 R123 R124 U17 U21 U22 U26 U28 U30
component class HW_Mechanical_Parts: H1 H2 H3 H4 HW6 HW8
component class PoE: C1 C2 C3 C4 C5 C6 C7 C8 C9 C10 C11 C12 C13 C14 C16 C17 C19 C20 C25 C26 C28 C29 C30 C31 C32 C40 C52 C55 C57 C60 C61 C62 C98 C109 C123 C127 D1 D2 D3 D4 D5 D6 D7 L1 R1 R2 R4 R5 R6 R8 R10 R11 R12 R14 R15 R17 R18 R20 R21 R26 R27 R28 R33 R34 R40 R44 R54 R61 R67 R69 R74 R80 R82 R139 T2 T3 T4 U3 U8 U10
component class Power: C16 C18 C22 C25 C29 C37 C44 C46 C51 C52 C57 C58 C73 C85 C87 C93 C94 C95 C96 C97 C107 C119 C120 C121 C122 C123 C127 C128 C129 C130 C131 C133 C134 C137 C151 C184 C300 C301 HW14 JP1 L2 L3 L4 R16 R139 R306 SB3 SB8 SB13 SB15 SB17 SB18 SB19 SB20 SB22 SB23 SB25 TP1 TP4 TP5 U1 U12 U17 U26 U300
component class U_HyperRAM: C136 C140 R65 R300 SB22 U7
component class STlink_V3E_PWR: C22 C37 C46 C67 C73 C81 C92 C94 C97 C101 C102 C103 C105 C106 C113 C114 C119 C122 C132 C142 C144 C145 C146 C147 C148 C149 C151 C155 D8 D9 D10 D11 D13 JP7 LD3 LD4 R55 R105 R125 R126 R127 U24 U26
component class STMod+: B2 C82 CN19 LD1 LD2 P1 P2 R140 R141 R142 R144 R149 SB6 SB8 SB10 SB11 SB12 SB13 SB19 SB30 U31
component class TAG: R147 R148 R150 R151 R152 R153
component class STlink_V3E_Module: C67 C71 C72 C104 C115 CN7 CN8 CN15 JP2 JP3 LD2 R17 R25 R54 R56 R60 R88 R89 R103 R106 R107 R108 R109 R110 R111 R112 R113 R130 R146 R300 R301 R302 R303 R304 R305 TP4 U4 U16 U26 U29 U30 X3
component class U_MCU: B2 C87 C121 C122 C142 CN3 HW12 HW13 R17 R21 R24 R25 R35 R37 R38 R39 R40 R41 R44 R45 R46 R48 R53 R54 R60 R61 R62 R63 R64 R77 R80 R82 R83 R93 R95 R98 R100 R101 R136 R139 R149 R302 R303 R304 SB5 SB22 SB29 SB30 SW1 U6 U31 X1 X2
component class USB_OTG_FS: C112 CN15 LD1 LD4 Q1 R74 R116 R117 R118 R128 R132 R133 R135 U24 U25
component class "Components Class 2": C136 C140
net class HyperRAM: NetR38_1 NetR39_1 NetR40_1 NetR45_2 NetR46_2 NetR48_1 NetR52_2 NetR53_2 NetR60_2 NetR66_1 NetR83_2
net class Iso_Diff: NetCN3_2 NetCN3_3 NetCN3_6 NetCN5_1 NetR25_2 NetR32_2 NetR58_2 NetR59_2 RD_N RD_P RMII_RXD0 RMII_RXD1 RMII_TXD0 RMII_TXD1 TD_N TD_P USB_DEV_HS_CN_N USB_DEV_HS_CN_P USB_DEV_HS_N USB_DEV_HS_P USB_FS_DM USB_FS_DP
net class Alim: 1V8 3V3 3V3_STLK 5V 5V_POE 5V_USB_CHGR 5V_USB_STLK AGND Chassis E5V GNDDetect POE7 USB_FS_VBUS VDD_ETH VDD_MCU VDD_SDC VDDA VIN VREF+
differential pair ARD_A: +ARD_A2 -ARD_A3
differential pair RMII_TXD_R: +NetR25_2 -NetR32_2
differential pair RD_CN: +NetCN3_3 -NetCN3_6
differential pair TD_CN: +NetCN3_1 -NetCN3_2
differential pair RMII_RXD_R: +NetR58_2 -NetR59_2
differential pair RMII_RXD: +RMII_RXD0 -RMII_RXD1
differential pair RMII_TXD: +RMII_TXD0 -RMII_TXD1
differential pair TD: +TD_P -TD_N
differential pair RD: +RD_P -RD_N
differential pair USB_DEV_HS: +USB_DEV_HS_P -USB_DEV_HS_N
differential pair USB_DEV_HS_CN: +USB_DEV_HS_CN_P -USB_DEV_HS_CN_N
differential pair USB_FS: +USB_FS_DP -USB_FS_DM

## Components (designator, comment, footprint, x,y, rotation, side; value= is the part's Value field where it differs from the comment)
B1 "SW-PUSH-CMS" SWI_WEALTHMETAL_TD-0341_4P_BLACK 152.175,70.5 r180 bottom value=SWITCH
B2 "SW-PUSH-CMS" SWI_WEALTHMETAL_TD-0341_4P_BLUE 152.175,56.7 r180 bottom value=SWITCH
C1 "Capacitor" C1210 101.461,84.389 r270 top value=4.7uF
C2 "Capacitor" C1210 104.586,84.389 r270 top value=4.7uF
C3 "Capacitor" C0805 72.811,85.114 r270 top value=47uF
C4 "Capacitor" C0805 74.611,85.114 r270 top value=47uF
C5 "Capacitor" C0805 76.436,85.114 r270 top value=47uF
C6 "Capacitor" C0603 78.086,85.014 r270 top value=100nF
C7 "Capacitor" C0805 98.736,84.439 r270 top value=100nF
C8 "Capacitor" C0603 128.386,84.214 r0 top value=1nF
C9 "Capacitor" C0805 128.961,82.039 r270 top value=100nF
C10 "Capacitor" C1206_H1P6 107.286,79.614 r270 top value=1nF
C11 "Capacitor" C0805 73.611,80.314 r90 top value=47uF
C12 "Capacitor" C0603 75.436,80.289 r90 top value=560pF
C13 "Capacitor" C0603 128.411,79.889 r180 top value=1nF
C14 "Capacitor" C0603 101.211,77.214 r180 top value=27pF
C15 "Capacitor" C0603 131.711,76.964 r180 top value=1nF
C16 "Capacitor" C0603 106.336,76.089 r270 top value=1nF
C17 "Capacitor" C0603 107.711,76.089 r270 top value=1nF
C18 "Capacitor" C1210 101.661,74.914 r180 top value=4.7uF
C19 "Capacitor" C0603 136.786,75.164 r0 top value=1nF
C20 "Capacitor" C0603 131.711,75.089 r180 top value=1nF
C21 "Capacitor" C0603 78.211,73.739 r270 top value=1uF
C22 "Capacitor" C0603 64.225,71.875 r270 top value=2.2uF
C23 "Capacitor" C0402 62.775,71.675 r90 top value=4.7uF
C24 "Capacitor" C0603 46.425,70.125 r270 top value=4.7uF
C25 "Capacitor" C0603 89.461,70.339 r180 top value=1uF
C26 "Capacitor" C1210 76.375,68.325 r270 top value=22uF
C27 "Capacitor" C0603 87.461,68.239 r90 top value=100pF
C28 "Capacitor" C0603 100.586,67.839 r0 top value=100nF
C29 "Capacitor" C0603 89.461,67.539 r0 top value=22nF
C30 "Capacitor" C1206_H1P6 96.759,65.91 r180 top value=1nF
C31 "Capacitor" C0603 89.461,66.164 r180 top value=10nF
C32 "Capacitor" C0402 75.425,63.975 r180 top value=100nF
C33 "Capacitor" C0603 113.011,60.964 r90 top value=22nF
C34 "Capacitor" C0402 115.4,61.3 r180 top value=100nF
C35 "Capacitor" C0402 75.6,60.8 r270 top value=10uF
C36 "Capacitor" C0402 115.4,60.25 r180 top value=100nF
C37 "Capacitor" C0402 79.35,59.65 r180 top value=100nF
C38 "Capacitor" C0603 80.875,57.525 r90 top value=10uF
C39 "Capacitor" C0603 100.461,56.839 r270 top value=470pF
C40 "Capacitor" C0603 103.211,56.839 r270 top value=100nF
C41 "Capacitor" C0603 104.586,56.839 r270 top value=100nF
C42 "Capacitor" C0603 105.961,56.839 r270 top value=1uF
C43 "Capacitor" C0402 78.075,56.75 r180 top value=220pF
C44 "Capacitor" C0603 55.25,55.475 r0 top value=2.2uF
C45 "Capacitor" C0402 78.275,55.2 r90 top value=1.5pF
C46 "Capacitor" C0402 117.2,54.425 r90 top value=100nF
C47 "Capacitor" C0402 55.1,54.025 r180 top value=4.7uF
C48 "Capacitor" C0402 78.275,53.3 r270 top value=1.5pF
C49 "Capacitor" C0603 134.675,53 r0 top value=100nF
C50 "Capacitor" C0603 121.55,52.7 r180 top value=1uF
C51 "Capacitor" C0402 121.55,51.55 r180 top value=470pF
C52 "Capacitor" C0603 106.157,49.146 r270 top value=1nF
C53 "Capacitor" C0603 67.65,49 r90 top value=2.2uF
C54 "Capacitor" C0402 68.85,49.325 r270 top value=4.7uF
C55 "Capacitor" C0402 121.55,47.425 r0 top value=100nF
C56 "Capacitor" C0603 121.55,46.275 r180 top value=10uF
C57 "Capacitor" C0603 98.961,45.464 r270 top value=100nF
C58 "Capacitor" C0603 100.336,45.464 r270 top value=10nF
C59 "Capacitor" C0603 101.711,45.464 r270 top value=1nF
C60 "Capacitor" C0603 104.961,45.464 r90 top value=10nF
C61 "Capacitor" C0402 114.125,44.825 r270 top value=100nF
C62 "Capacitor" C0402 111.425,43.725 r0 top value=100nF
C63 "Capacitor" C0402 104.886,38.989 r0 top value=100nF
C64 "Capacitor" C0603 33.75,38.125 r270 top value=2.2uF
C65 "Capacitor" C0603 35.125,38.125 r270 top value=2.2uF
C66 "Capacitor" C0603 36.5,38.125 r270 top value=2.2uF
C67 "Capacitor" C1206_H1P15 120.381,36.55 r270 top value=2.2uF
C68 "Capacitor" C0402 39.1,37.8 r90 top value=100nF
C69 "Capacitor" C0402 40.025,37.8 r90 top value=100nF
C70 "Capacitor" C0603 104.886,37.839 r0 top value=1uF
C71 "Capacitor" C0603 118.411,36.464 r270 top value=2.2uF
C72 "Capacitor" C0402 112.236,36.389 r90 top value=20pF
C73 "Capacitor" C0603 100.586,35.714 r270 top value=1uF
C74 "Capacitor" C0603 33.25,36.125 r0 top value=4.7uF
C75 "Capacitor" C0402 101.811,35.714 r90 top value=100nF
C76 "Capacitor" C0402 106.986,34.739 r270 top value=10nF
C77 "Capacitor" C0402 33.575,34.975 r180 top value=100nF
C78 "Capacitor" C0603 33.25,33.825 r180 top value=1uF
C79 "Capacitor" C0603 43.975,32.875 r180 top value=1uF
C80 "Capacitor" C0603 33.25,32.45 r0 top value=4.7uF
C81 "Capacitor" C0402 43.65,31.725 r0 top value=100nF
C82 "Capacitor" C0402 33.575,31.3 r180 top value=100nF
C83 "Capacitor" C0603 43.975,30.575 r180 top value=1uF
C84 "Capacitor" C0603 33.25,30.15 r0 top value=4.7uF
C85 "Capacitor" C0402 48.45,29.875 r0 top value=10nF
C86 "Capacitor" C0402 43.65,29.425 r0 top value=100nF
C87 "Capacitor" C0402 54.025,28.45 r270 top value=1uF
C88 "Capacitor" C0603 43.975,28.275 r180 top value=4.7uF
C89 "Capacitor" C0603 35.5,27.5 r270 top value=1uF
C90 "Capacitor" C0603 36.875,27.5 r270 top value=1uF
C91 "Capacitor" C0603 38.25,27.5 r90 top value=4.7uF
C92 "Capacitor" C0603 39.625,27.5 r90 top value=4.7uF
C93 "Capacitor" C0402 48.9,27.5 r90 top value=1uF
C94 "Capacitor" C0805 84.25,25.375 r0 top value=10uF
C95 "Capacitor" C0402 97.85,24.775 r180 top value=100nF
C96 "Capacitor" C0805 97.85,23.375 r0 top value=10uF
C97 "Capacitor" C0805 84.25,23.075 r0 top value=10uF
C98 "capacitor" C0402 53.775,22.775 r180 top value=100nF
C99 "Capacitor" C0402 61.775,22.775 r180 top value=100nF
C100 "Capacitor" C0402 70.275,22.775 r180 top value=100nF
C101 "Capacitor" C0603 120.836,20.839 r90 top value=4.7uF
C102 "Capacitor" C0603 122.211,20.839 r90 top value=1uF
C103 "Capacitor" C0402 111.986,20.789 r90 top value=100nF
C104 "Capacitor" C0402 114.811,20.789 r90 top value=100nF
C105 "Capacitor" C0402 118.736,20.789 r90 top value=100nF
C106 "Capacitor" C0402 119.686,20.789 r90 top value=100nF
C107 "Capacitor" C0603 100.825,20.875 r180 top value=4.7uF
C108 "Capacitor" C0402 110.286,19.214 r0 top value=100nF
C109 "Capacitor" C0402 51.875,14.075 r90 top value=100nF
C110 "Capacitor" C0402 59.875,14.075 r90 top value=100nF
C111 "Capacitor" C0402 68.375,14.075 r90 top value=100nF
C112 "Cap_POL_TANA" CPOL_VISHAY_TANTAL-595D_1407_H220 88.375,12.4 r270 top value=4.7uF
C113 "Capacitor" C0603 113.725,12.5 r270 top value=1uF
C114 "Capacitor" C0603 107.336,12.139 r0 top value=1uF
C115 "Capacitor" C0402 110.061,7.164 r270 top value=100pF
C116 "Capacitor" C0402 94.725,84.8 r90 bottom value=100nF
C117 "Capacitor" C0402 83.8,84.525 r180 bottom value=100nF
C118 "Capacitor" C0402 92.825,76.1 r0 bottom value=100nF
C119 "Capacitor" C0805 92.825,74.65 r180 bottom value=10uF
C120 "Capacitor" C0805 72.4,65.775 r270 bottom value=10uF
C121 "Capacitor" C0402 71.025,65.175 r270 bottom value=100nF
C122 "Capacitor" C0402 70.125,65.175 r270 bottom value=100nF
C123 "Capacitor" C0402 69.2,65.175 r90 bottom value=1uF
C124 "Capacitor" C0402 65.9,64.775 r0 bottom value=100nF
C125 "Capacitor" C0402 63.7,63 r90 bottom value=100nF
C126 "Capacitor" C0402 69.075,63.375 r0 bottom value=100nF
C127 "Capacitor" C0402 70.05,61.75 r90 bottom value=100nF
C128 "Capacitor" C0402 63.275,61.5 r0 bottom value=100nF
C129 "Capacitor" C0402 69.25,59.95 r0 bottom value=100nF
C130 "Capacitor" C0603 62.325,59.55 r180 bottom value=1uF
C131 "Capacitor" C0402 71.275,58.65 r180 bottom value=100nF
C132 "Capacitor" C0402 32.075,58.25 r0 bottom value=100nF
C133 "Capacitor" C0402 63.9,58.225 r0 bottom value=100nF
C134 "Capacitor" C0402 69.125,57.6 r0 bottom value=100nF
C135 "Capacitor" C0402 65.55,57.6 r180 bottom value=100nF
C136 "Capacitor" C0402 37.425,56.925 r90 bottom value=100nF
C137 "Capacitor" C0402 65.55,56.675 r180 bottom value=4.7uF
C138 "Capacitor" C0402 147.325,55.4 r0 bottom value=100nF
C139 "Capacitor" C0402 34.125,54.19 r180 bottom value=100nF
C140 "Capacitor" C0402 61.775,37.825 r180 bottom value=100nF
C141 "Capacitor" C0402 65,33.55 r270 bottom value=100nF
C142 "Capacitor" C1206_H1P15 115.025,32.925 r180 bottom value=2.2uF
C143 "Capacitor" C0402 59.575,32.55 r90 bottom value=100nF
C144 "Capacitor" C0402 116.8,30.55 r90 bottom value=100nF
C145 "Capacitor" C0402 115.625,30.55 r90 bottom value=100nF
C146 "Capacitor" C0402 114.75,30.55 r90 bottom value=100nF
C147 "Capacitor" C0402 113.875,30.55 r90 bottom value=100nF
C148 "Capacitor" C0402 119.95,29.9 r180 bottom value=100nF
C149 "Capacitor" C0402 119.95,29.025 r180 bottom value=100nF
C150 "Capacitor" C0402 110.575,28.975 r0 bottom value=100nF
C151 "Capacitor" C0402 119.95,28.1 r180 bottom value=100nF
C152 "Capacitor" C0402 110.575,28.025 r0 bottom value=100nF
C153 "Capacitor" C0402 110.575,27.1 r0 bottom value=100nF
C154 "Capacitor" C0402 116.875,26.075 r270 bottom value=100nF
C155 "Capacitor" C0402 110.575,26.175 r0 bottom value=100nF
C156 "Capacitor" C0402 114.9,24.125 r90 bottom value=100nF
C157 "Capacitor" C0402 112.975,24.125 r90 bottom value=100nF
C158 "Capacitor" C0402 36.549,7.198 r90 bottom value=100nF
CN1 "SMA-J-P-H-ST-EM1" CON_SAMTEC_SMA-J-P-X-ST-EM1 62.725,88 r180 top value=Jack_SMA_SMA-J-P-H-ST-EM1
CN2 "microSD-PJS008-2003" CON_MICROSD_YAMAICHI_PJS008-2003-1 47.2,88 r90 top value=uSD-Card_PJS008-2003-1
CN3 "RJ45_KRJ-CB4.2GYZNL" CON_RJ45_DGKYD_KRJ-CB4.2GYZNL 117.3,88.025 r180 top
CN4 "Socket 10x1" CON_SAMTEC_SSW-110-22-X-S-VS 126.086,45.214 r270 top
CN5 "Socket 8x1" CON_SAMTEC_SSW-108-22-X-S-VS 77.826,38.61 r90 top
CN6 "Header 4x1" CON_SAMTEC_TSW-104-07-G-S 153.581,30.157 r270 top
CN7 "Header 7x2" CON_STDC14_Receiver_MEDIUM_WITH_MIPI10_3D 5.511,25.339 r270 top value="Header 5x2"
CN8 "Socket 8x1" CON_SAMTEC_SSW-108-22-X-S-VS 126.086,20.83 r270 top
CN9 "Socket 6x1" CON_SAMTEC_SSW-106-22-X-S-VS 77.826,18.29 r90 top
CN10 "Jack_PJ3028B-3_3P" CON_PHONE-JACK-3P5_HY_PJ3028B 32.225,0 r90 top value=Jack_Socket-Stereo_PJ3028B-3_GR
CN11 "Jack_PJ3028B-3_3P" CON_PHONE-JACK-3P5_HY_PJ3028B 44.55,0 r90 top value=Jack_Socket-Stereo_PJ3028B-3_BE
CN12 "Jumper_Header 2x1" CON_SAMTEC_TSW-102-07-G-S 18.453,5.613 r90 top value="Header 2x1"
CN13 "Jumper_Header 2x1" CON_SAMTEC_TSW-102-07-G-S 23.533,5.613 r90 top value="Header 2x1"
CN14 "USB_uAB_47590.0001" CON_USBMICROAB_MOLEX_47590-0001_H3 83.775,0 r0 top
CN15 "USB_uB_105017.0001" CON_USBMICROB_MOLEX_105017-0001_H2P90 114.775,0 r0 top value=USB_uB_105017-0001
CN16 "Header 2x1" CON_988-JIUBABA_PHFS25-11-02-G0B115-T-1 53.85,3.475 r180 top value="header 2x1"
CN17 "Header 2x1" CON_988-JIUBABA_PHFS25-11-02-G0B115-T-1 62.1,3.475 r180 top value="header 2x1"
CN18 "Header 2x1" CON_988-JIUBABA_PHFS25-11-02-G0B115-T-1 70.85,3.475 r180 top value="header 2x1"
CN19 "Header 25x2" MOD_LCD_MB1046B__CON_SAMTEC_FLE-125-01-G-DV 79.5,88 r180 bottom locked
CN20 "Socket 10x2" CON_FCI_20021311-XXX20XXLF 7.06,42.037 r90 bottom locked
CN21 "Tag-10-C" CON_TAG-C_TC2050-IDC-NL 7.125,14.45 r180 bottom value="Header 5x2"
D1 "SMAJ58A-TR" DIO_SMA_1A_2K 131.561,82.189 r270 top
D2 "STPS2L40UF" DIO_SMB-FLAT_1A_2K 78.711,78.539 r270 top
D3 "DIODE_1A_2K" DIO_SOD323_1A_2K 104.436,79.914 r270 top value=BAT46JFILM
D4 "DF01S" BRF_VISHAY_DFS_DF01S 127.886,67.964 r0 top value=DF01S-E3/77
D5 "DF01S" BRF_VISHAY_DFS_DF01S 136.911,67.964 r0 top value=DF01S-E3/77
D6 "DIODE_1A_2K" DIO_SOD323_1A_2K 98.661,60.364 r180 top value=BAT46JFILM
D7 "SMAJ58A-TR" DIO_SMA_DO214-AC_1A_2K 108.836,51.239 r270 top value=STPS1H100A
D8 "BAT60JFILM" DIO_SOD323 99.236,31.014 r90 top
D9 "BAT60JFILM" DIO_SOD323 101.186,31.014 r90 top
D10 "BAT60JFILM" DIO_SOD323 103.111,31.014 r90 top
D11 "BAT60JFILM" DIO_SOD323 105.014,31.014 r90 top
H1 "POSITION HOLE" PTH_350_700 5,83 r0 top
H2 "POSITION HOLE" PTH_350_700 154,83 r0 top
H3 "POSITION HOLE" PTH_350_700 5,5 r0 top
H4 "POSITION HOLE" PTH_350_700 154,5 r0 top
JP1 "Jumper_Header 2x1 Fitted" CON_SAMTEC_TSW-102-07-G-S 61.35,46.975 r180 top value="Header 2x1"
JP2 "Jumper_Header 2x1" CON_SAMTEC_TSW-102-07-G-S 19.901,32.385 r180 top value="Header 2x1"
JP3 "Jumper_Header 2x1" CON_SAMTEC_TSW-102-07-G-S 153.277,18.517 r180 top value="Header 2x1"
JP4 "Jumper_Header 2x1" CON_SAMTEC_TSW-102-07-G-S 53.95,10.45 r180 top value="Header 2x1"
JP5 "Jumper_Header 2x1" CON_SAMTEC_TSW-102-07-G-S 61.95,10.45 r180 top value="Header 2x1"
JP6 "Jumper_Header 2x1" CON_SAMTEC_TSW-102-07-G-S 70.7,10.45 r180 top value="Header 2x1"
JP7 "Header 5x2" CON_988-JIUBABA_PHFS25-12-10-G0B115-T-1 99.375,4.675 r180 top
L1 "Inductor" IND_POWER_COILCRAFT_ME3220 101.511,71.614 r0 top value=5.6uH
L2 "Inductor" IND_TAIYO-YUDEN_FBMJ1608 76.825,60.725 r270 top value="18R @ 100MHz"
L3 "Inductor" IND_2016_MURATA_LQM2MPN2R2NG0 76.075,57.55 r270 top value=2.2uH
L4 "BEAD" L0603 111.075,44.95 r180 top value="600R @ 100MHz"
L5 "BEAD" L0603 71.9,61.5 r180 bottom value="600R @ 100MHz"
LD1 "LED_green" LED_0603_GREEN 153.7,44.075 r180 bottom value=Green
LD2 "LED_red" LED_0603_RED 153.7,46.3 r180 bottom value=Red
LD3 "LED_red" LED_0603_VISHAY_VLMS1300-GS08_RED_1A2K_H0P8 116.311,13.064 r180 top value=RED
LD4 "LED_green" LED_0603_GREEN 80.05,6.925 r90 top value=Green
LD5 "LED_green" LED_0603_VISHAY_VLMTG1300-GS08_GREEN_1A2K_H0P8 107.611,6.514 r90 top value="TRUE GREEN"
LD6 "LD_BICOLOR_CMS" LED_BI-GR_HSMF-A201-A00J1 120.086,13.689 r180 top
LD7 "LED_red" LED_0603_RED 92.901,16.688 r180 top value=Red
LD8 "LED_green" LED_0603_GREEN 153.675,42.075 r0 bottom value=Green
MIRE1 "Comment" MIRE_PLACE_SMD_0P8MM 11.375,85.725 r270 top
MIRE2 "Comment" LOGO_ETIQUETTE 148.3,77.475 r270 top
MIRE3 "Comment" LOGO_ETIQUETTE 18,61.85 r270 top
MIRE4 "Comment" MIRE_PLACE_SMD_0P8MM 148.45,2 r270 top
MIRE5 "Comment" MIRE_PLACE_SMD_0P8MM 11.075,2.95 r270 top
MIRE6 "Comment" MIRE_PLACE_SMD_0P8MM 147.6,83.85 r270 bottom
MIRE7 "Comment" MIRE_PLACE_SMD_0P8MM 10.8,81.35 r270 bottom
MIRE8 "Comment" MIRE_PLACE_SMD_0P8MM 147.05,6.775 r270 bottom
P1 "Socket 6X2 PMOD" CON_SAMTEC_SSW-106-02-F-D-RA__PMOD 21.7,76.35 r0 bottom value="Socket 6X2"
P2 "Socket 10X2 STMod+" CON_SAMTEC_SQT-110-01-F-D-RA__STMOD+ 8.975,63 r90 bottom value="Socket 10X2"
Q1 "9013-SOT23" NPN_SOT23 76.175,7.525 r0 top value="NPN SOT23"
R1 "Resistor" R0805 107.211,84.664 r90 top value=0R
R2 "Resistor" R0603 79.711,83.339 r90 top value=0R
R3 "Resistor" R0603 37.35,81.9 r270 top value=10K
R4 "Resistor" R0805 101.386,81.214 r180 top value=68R
R5 "Resistor" R1206_H0P55 101.386,79.114 r180 top value=200R
R6 "Resistor" R0402 128.382,78.483 r180 top value=330R
R7 "Resistor" R0805 75.436,77.089 r90 top value=15R
R8 "Resistor" R0603 103.961,77.189 r0 top value=10K
R9 "Resistor" R0805 128.763,76.959 r180 top value=75R
R10 "Resistor" R0805 134.361,76.039 r90 top value=0R
R11 "Resistor" R0805 139.461,76.039 r90 top value=0R
R12 "Resistor" R0805 128.761,75.089 r180 top value=75R
R13 "Resistor" R0402 110.6,74.55 r90 top value=330R
R14 "Resistor" R0805 106.711,73.264 r270 top value=75R
R15 "Resistor" R0805 108.586,73.264 r270 top value=75R
R16 "Resistor" R0402 79.536,73.689 r270 top value=120K
R17 "Resistor" R0805 104.761,71.614 r90 top value=10R
R18 "Resistor" R0805 89.536,71.964 r180 top value=0R
R19 "Resistor" R0603 84.711,72.164 r180 top value=13K
R20 "Resistor" R0603 87.111,71.689 r90 top value=20K
R21 "Resistor" R0603 84.711,70.739 r0 top value=13K
R22 "Resistor" R0603 100.586,69.214 r180 top value=1K
R23 "Resistor" R0603 89.461,68.939 r0 top value=10K
R24 "Resistor" R0402 65.475,68.675 r270 top value=33R
R25 "Resistor" R0402 59.2,65.9 r0 top value=33R
R26 "Resistor" R0603 89.461,64.764 r0 top value=1K
R27 "Resistor" R0402 42.45,64.575 r270 top value=47K
R28 "Resistor" R0402 43.525,64.575 r270 top value=47K
R29 "Resistor" R0402 44.75,64.575 r270 top value=47K
R30 "Resistor" R0402 48.475,64.575 r270 top value=47K
R31 "Resistor" R0402 49.55,64.575 r270 top value=47K
R32 "Resistor" R0402 59.2,64.825 r0 top value=33R
R33 "Resistor" R0805 97.961,63.014 r90 top value=0R
R34 "Resistor" R0805 99.836,63.014 r270 top value=56R
R35 "Resistor" R0402 76.975,63.3 r270 top value=51R
R36 "Resistor" R0402 75.425,62.975 r180 top value=51R
R37 "Resistor" R0402 32.975,61.675 r90 top value=33R
R38 "Resistor" R0402 34.05,61.675 r270 top value=33R
R39 "Resistor" R0402 35.125,61.675 r270 top value=33R
R40 "Resistor" R0402 36.2,61.675 r270 top value=33R
R41 "Resistor" R0402 81.525,61.3 r90 top value=10K
R42 "Resistor" R0805 119.361,60.639 r270 top value=0R
R43 "Resistor" R1206_H0P55 108.511,59.514 r180 top value=0R47
R44 "Resistor" R0603 98.711,58.689 r0 top value=10K
R45 "Resistor" R0402 29.7,58.6 r180 top value=33R
R46 "Resistor" R0402 38.3,58.025 r0 top value=33R
R47 "Resistor" R0603 101.811,56.839 r90 top value=510R
R48 "Resistor" R0402 29.7,57.35 r0 top value=33R
R49 "Resistor" R0402 118.2,56.525 r90 top value=10K
R50 "Resistor" R0402 119.275,56.525 r90 top value=10K
R51 "Resistor" R0402 115.125,56.15 r270 top value=10K
R52 "Resistor" R0402 29.7,56.025 r180 top value=33R
R53 "Resistor" R0402 38.3,55.9 r0 top value=120R
R54 "Resistor" R0603 76.625,54.975 r0 top value=0R
R55 "Resistor" R0402 114.05,54.425 r90 top value=1K5
R56 "Resistor" R0402 115.125,54.425 r270 top value=33R
R57 "Resistor" R0402 116.2,54.425 r90 top value=10K
R58 "Resistor" R0402 118.2,54.425 r270 top value=33R
R59 "Resistor" R0402 119.275,54.425 r270 top value=33R
R60 "Resistor" R0402 38.3,54.65 r0 top value=120R
R61 "Resistor" R0603 106.157,53.337 r270 top value=0R
R62 "Resistor" R0603 76.625,53.525 r0 top value=0R
R63 "Resistor" R0402 71.85,52.2 r90 top value=10K
R64 "Resistor" R0402 72.9,52.2 r90 top value=10K
R65 "Resistor" R0402 34.525,51.2 r270 top value=10K
R66 "Resistor" R0402 35.7,51.195 r90 top value=33R
R67 "Resistor" R0402 112.075,50.725 r0 top value=10K
R68 "Resistor" R0402 121.55,50.55 r180 top value=100R
R69 "Resistor" R0603 98.918,49.146 r90 top value=124K
R70 "Resistor" R0402 121.55,49.475 r0 top value=10K
R71 "Resistor" R0402 121.55,48.4 r180 top value=10K
R72 "Resistor" R0603 73.211,47.514 r0 top value=1K
R73 "Resistor" R0603 136.361,45.789 r270 top value=1M
R74 "Resistor" R0805 103.336,45.139 r90 top value=2K
R75 "Resistor" R0603 106.361,45.464 r90 top value=75K
R76 "Resistor" R0402 115.125,44.825 r270 top value=49R9
R77 "Resistor" R0402 116.2,44.825 r270 top value=49R9
R78 "Resistor" R0402 117.275,44.825 r270 top value=49R9
R79 "Resistor" R0402 118.35,44.825 r270 top value=49R9
R80 "Resistor" R0402 119.4,44.825 r270 top value=12K1
R81 "Resistor" R0402 63.15,38.925 r90 top value=10K
R82 "Resistor" R0402 64.225,38.925 r270 top value=33R
R83 "Resistor" R0402 65.3,38.925 r90 top value=33R
R84 "Resistor" R0603 37.9,38.125 r90 top value=20R
R85 "Resistor" R0603 41.225,38.125 r90 top value=20R
R86 "Resistor" R0603 42.65,38.125 r270 top value=4K7
R87 "Resistor" R0402 57.45,37.05 r0 top value=33R
R88 "Resistor" R0402 113.236,36.389 r90 top value=100R
R89 "Resistor" R0402 117.111,36.389 r270 top value=3K
R90 "Resistor" R0402 43.65,36.225 r0 top value=1K5
R91 "Resistor" R0402 57.45,35.975 r0 top value=33R
R92 "Resistor" R0402 43.65,35.15 r0 top value=1K5
R93 "Resistor" R0402 57.45,34.9 r0 top value=33R
R94 "Resistor" R0402 43.65,34.1 r180 top value=10K
R95 "Resistor" R0402 57.45,33.775 r0 top value=33R
R96 "Resistor" R0402 57.45,32.65 r0 top value=33R
R97 "Resistor" R0402 121.761,31.439 r0 top value=100R
R98 "Resistor" R0402 60.15,30.2 r90 top value=33R
R99 "Resistor" R0402 61.225,30.2 r90 top value=33R
R100 "Resistor" R0402 62.3,30.2 r270 top value=33R
R101 "Resistor" R0402 63.375,30.2 r270 top value=33R
R102 "Resistor" R0402 67.675,30.35 r0 top value=10K
R103 "Resistor" R0402 14.261,27.939 r0 top value=22R
R104 "Resistor" R0402 14.261,26.739 r0 top value=22R
R105 "Resistor" R0402 121.761,25.989 r180 top value=10K
R106 "Resistor" R0402 14.261,25.489 r0 top value=22R
R107 "Resistor" R0402 121.761,24.939 r180 top value=2K7
R108 "Resistor" R0402 14.261,24.239 r0 top value=22R
R109 "Resistor" R0402 121.761,23.864 r180 top value=4K7
R110 "Resistor" R0402 14.175,21.175 r0 top value=22R
R111 "Resistor" R0402 113.811,20.789 r90 top value=100R
R112 "Resistor" R0402 116.661,20.789 r270 top value=4K7
R113 "Resistor" R0402 117.736,20.789 r270 top value=4K7
R114 "Resistor" R0402 14.175,20 r180 top value=22R
R115 "Resistor" R0402 110.286,17.964 r0 top value=10K
R116 "Resistor" R0402 89.9,16.675 r90 top value=0R
R117 "Resistor" R0402 90.975,16.675 r90 top value=47K
R118 "Resistor" R0402 95.187,16.764 r0 top value=620R
R119 "Resistor" R0402 53.125,14.075 r270 top value=120R
R120 "Resistor" R0402 55.675,14.075 r270 top value=10K
R121 "Resistor" R0402 61.15,14.075 r270 top value=120R
R122 "Resistor" R0402 63.675,14.075 r270 top value=10K
R123 "Resistor" R0402 69.625,14.075 r270 top value=120R
R124 "Resistor" R0402 72.175,14.075 r270 top value=10K
R125 "Resistor" R0402 113.886,14.364 r0 top value=47K
R126 "Resistor" R0402 116.261,14.364 r180 top value=1K
R127 "Resistor" R0402 107.661,14.064 r180 top value=10K
R128 "Resistor" R0402 95.175,13.025 r180 top value=0R
R129 "Resistor" R0402 95.175,11.95 r180 top value=10K
R130 "Resistor" R0603 119.336,9.964 r270 top value=330R
R131 "Resistor" R0603 120.836,9.964 r270 top value=330R
R132 "Resistor" R0402 78.9,6.625 r90 top value=330R
R133 "Resistor" R0402 76.2,5.025 r0 top value=22K
R134 "Resistor" R0603 107.611,3.839 r90 top value=1K
R135 "Resistor" R0402 76.2,3.95 r0 top value=47K
R136 "Resistor" R0402 83.8,85.55 r0 bottom value=0R
R137 "Resistor" R0603 95.075,75.35 r270 bottom value=0R
R138 "Resistor" R0603 90.6,75.35 r270 bottom value=0R
R139 "Resistor" R0603 71.6,63.05 r180 bottom value=0R
R140 "Resistor" R0402 147.325,56.4 r0 bottom value=100R
R141 "Resistor" R0402 147.325,54.4 r180 bottom value=330R
R142 "Resistor" R0402 147.325,53.35 r0 bottom value=220K
R143 "Resistor" R0603 150.625,46.3 r0 bottom value=680R
R144 "Resistor" R0603 150.625,44.075 r0 bottom value=510R
R145 "Resistor" R0603 150.625,42.075 r180 bottom value=510R
R146 "Resistor" R0402 2.836,22.789 r180 bottom value=100R
R147 "Resistor" R0402 14.55,16.9 r180 bottom value=22R
R148 "Resistor" R0402 14.55,15.85 r180 bottom value=22R
R149 "Resistor" R0402 151.55,15 r0 bottom value=10K
R150 "Resistor" R0402 14.55,14.775 r180 bottom value=22R
R151 "Resistor" R0402 14.575,13.725 r180 bottom value=22R
R152 "Resistor" R0402 14.55,12.65 r180 bottom value=22R
R153 "Resistor" R0402 14.55,11.6 r180 bottom value=22R
R154 "Resistor" R0402 38.81,6.965 r180 bottom value=10K
SB1 "SB_ON" SOLDER-BRIDGE_R0603-0R 61.35,69.225 r270 top value="Solder Bridge ON"
SB2 "SB_ON" SOLDER-BRIDGE_R0603-0R 62.775,69.225 r270 top value="Solder Bridge ON"
SB3 "SB_ON" SOLDER-BRIDGE_R0603-0R 64.225,69.225 r270 top value="Solder Bridge ON"
SB4 "SB_ON" SOLDER-BRIDGE_R0603-0R 71.275,69.225 r270 top value="Solder Bridge ON"
SB5 "SB_ON" SOLDER-BRIDGE_R0603-0R 72.725,69.225 r270 top value="Solder Bridge ON"
SB6 "SB_ON" SOLDER-BRIDGE_R0603-0R 13.7,60.825 r180 bottom value="Solder Bridge ON"
SB7 "SB_ON" SOLDER-BRIDGE_R0603-0R 13.7,62.275 r180 bottom value="Solder Bridge ON"
SB8 "SB_ON" SOLDER-BRIDGE_R0603-0R 13.7,63.7 r180 bottom value="Solder Bridge ON"
SB9 "SB_ON" SOLDER-BRIDGE_R0603-0R 117.65,60.6 r270 top value="Solder Bridge ON"
SB10 "SB_ON" SOLDER-BRIDGE_R0603-0R 13.7,65.15 r180 bottom value="Solder Bridge ON"
SB11 "SB_ON" SOLDER-BRIDGE_R0603-0R 55.225,60.725 r0 top value="Solder Bridge ON"
SB12 "SB_ON" SOLDER-BRIDGE_R0603-0R 13.7,66.575 r180 bottom value="Solder Bridge ON"
SB13 "SB_ON" SOLDER-BRIDGE_R0603-0R 78.725,58.225 r180 top value="Solder Bridge ON"
SB14 "SB_ON" SOLDER-BRIDGE_R0603-0R 13.7,68.025 r180 bottom value="Solder Bridge ON"
SB15 "SB_ON" SOLDER-BRIDGE_R0603-0R 13.7,69.45 r180 bottom value="Solder Bridge ON"
SB16 "SB_ON" SOLDER-BRIDGE_R0603-0R 57.9,55.475 r0 top value="Solder Bridge ON"
SB17 "SB_ON" SOLDER-BRIDGE_R0603-0R 13.7,70.9 r180 bottom value="Solder Bridge ON"
SB18 "SB_ON" SOLDER-BRIDGE_R0603-0R 57.9,54.025 r0 top value="Solder Bridge ON"
SB19 "SB_ON" SOLDER-BRIDGE_R0603-0R 67.65,51.65 r90 top value="Solder Bridge ON"
SB20 "SB_ON" SOLDER-BRIDGE_R0603-0R 69.1,51.65 r90 top value="Solder Bridge ON"
SB21 "SB_ON" SOLDER-BRIDGE_R0603-0R 70.525,51.65 r90 top value="Solder Bridge ON"
SB22 "SB_ON" SOLDER-BRIDGE_R0603-0R 74.15,51.65 r90 top value="Solder Bridge ON"
SB23 "SB_ON" SOLDER-BRIDGE_R0603-0R 134.725,51.575 r0 top value="Solder Bridge ON"
SB24 "SB_ON" SOLDER-BRIDGE_R0603-0R 33.05,50.65 r90 top value="Solder Bridge ON"
SB25 "SB_ON" SOLDER-BRIDGE_R0603-0R 134.186,46.489 r180 top value="Solder Bridge ON"
SB26 "SB_ON" SOLDER-BRIDGE_R0603-0R 68.85,33.525 r180 top value="Solder Bridge ON"
SB27 "SB_ON" SOLDER-BRIDGE_R0603-0R 65.325,30.35 r0 top value="Solder Bridge ON"
SB28 "SB_ON" SOLDER-BRIDGE_R0603-0R 34.1,27.275 r90 top value="Solder Bridge ON"
SB29 "SB_ON" SOLDER-BRIDGE_R0603-0R 51.875,23.85 r90 top value="Solder Bridge ON"
SB30 "SB_ON" SOLDER-BRIDGE_R0603-0R 55.675,23.85 r90 top value="Solder Bridge ON"
SB31 "SB_ON" SOLDER-BRIDGE_R0603-0R 84.311,16.189 r180 top value="Solder Bridge ON"
SB32 "SB_ON" SOLDER-BRIDGE_R0603-0R 84.311,14.764 r180 top value="Solder Bridge ON"
SB33 "SB_ON" SOLDER-BRIDGE_R0603-0R 84.311,13.339 r180 top value="Solder Bridge ON"
SB34 "SB_ON" SOLDER-BRIDGE_R0603-0R 84.311,11.914 r180 top value="Solder Bridge ON"
SB35 "SB_ON" SOLDER-BRIDGE_R0603-0R 42.149,7.123 r180 bottom value="Solder Bridge ON"
SB36 "SB_ON" SOLDER-BRIDGE_R0603-0R 34.512,6.319 r90 bottom value="Solder Bridge ON"
SB37 "SB_ON" SOLDER-BRIDGE_R0603-0R 34.512,3.177 r270 bottom value="Solder Bridge ON"
SB38 "SB_ON" SOLDER-BRIDGE_R0603-0R 42.299,3.123 r0 bottom value="Solder Bridge ON"
SB39 "SB_ON" SOLDER-BRIDGE_R0603-0R 36.9,1.675 r0 bottom value="Solder Bridge ON"
SB40 "SB_ON" SOLDER-BRIDGE_R0603-0R 42.299,1.673 r0 bottom value="Solder Bridge ON"
SB41 "SB_ON" SOLDER-BRIDGE_R0603-0R 72.725,73.175 r90 top value="Solder Bridge ON"
SB42 "SB_ON" SOLDER-BRIDGE_R0603-0R 74.15,73.175 r90 top value="Solder Bridge ON"
SB43 "SB_ON" SOLDER-BRIDGE_R0603-0R 87.9,85.4 r90 bottom value="Solder Bridge ON"
SB44 "SB_ON" SOLDER-BRIDGE_R0603-0R 86.4,85.4 r90 bottom value="Solder Bridge ON"
SW1 "SW_MECA_1K2" SWI_EAO_09-03290-01_EXTENDED_STRAIGHT_BLACK 151.981,12.878 r90 bottom value="Mechanical Slide Switch 1K2"
T1 "TRS_750315923" TRS_WURTH_750315923 91.813,79.255 r180 top value=750315923
T2 "POE30P-50L" TRS_COILCRAFT_POE30P-50L 88.765,79.255 r180 top
T3 "H2019NL" TRS_PULSE_H2019NL 116.186,67.789 r0 top
T4 "STN4NF20L" MOS_SOT223-TAB 105.169,64.953 r0 top
T5 "BSN20" MOS_SOT23 139.186,45.789 r270 top value=BSN20BK
TP1 "Test Point" TP_SMD_0-3MM 56.4,68.4 r90 top
TP2 "Test Point" TP_SMD_0-3MM 87.4,53.725 r90 top
TP3 "Test Point" TP_SMD_1MM 112.261,41.514 r90 top value="Test Point 1mm"
TP4 "Test Point" TP_SMD_0-3MM 46.9,27.95 r180 top
TP5 "Test Point" TP_SMD_0-3MM 98.3,26.175 r270 top
U1 "REF6225IDGKT" ICC_VSSOP8_DGK_S-PDSO-G8_3X3_P065 79.875,69.2 r180 top
U2 "HMHA2801A" OPT_MINI-FLAT_FAIRCHILD_HMHA2801A 94.961,68.889 r90 top value=ACPL-217
U3 "TS431AILT" MOS_SOT23-5L 84.761,67.964 r0 top
U4 "HSP051-4M10" ESD_UQFN-10L_2P5X1_P050 43.725,66.825 r180 top
U5 "HSP051-4M10" ESD_UQFN-10L_2P5X1_P050 48.25,66.825 r180 top
U6 "STM32H725IGK6U" ICC_UFBGA201_176+25_10X10_P065 67.3,61.175 r180 top locked value=STM32H725IGK6
U7 "S70KL1281DABHI023" ICC_FBGA24_5X5-BALL-ARRAY_6X8_P1 34.05,56.425 r180 top locked value=IS66WVH16M8DBLL-100B1LI
U8 "PM8800ATR" ICC_HTSSOP16-EPAD_5X4P4_P065 102.576,51.196 r0 top
U9 "LAN8742A-CZ-TR" ICC_VQFN24-EPAD_4X4_P050 116.75,49.8 r180 top
U10 "MX25LM51245GXDI00" ICC_BGA24_5X5-BALL-ARRAY_6X8_P1 62.775,34.55 r270 top
U11 "LD3985M33R" REG_SOT23-5L 104.486,35.239 r270 top
U12 "WM8994ECS/R" ICC_W-CSP-BGA72_4P511X4P023_P050 38.225,32.875 r180 top
U13 "ST-LINKV3E_SWD" ICC_UFBGA201_176+25_10X10_P065 115.233,28.027 r90 top
U14 "LD3985M18R" REG_SOT23-5L 51.425,28.925 r90 top
U15 "LD1117S50TR" REG_SOT223-TAB 89.95,25.375 r270 top
U16 "ESDALC6V1W5" ESD_SOT323-5L 11.561,26.239 r0 top
U17 "ST1L05APU33R" ICC_DFN6-EPAD_3X3_P095 101.425,23.375 r270 top
U18 "ESDALC6V1W5" ESD_SOT323-5L 11.561,21.489 r0 top
U19 "ESDA6V1BC6" ESD_SOT23-6L 38.65,21.1 r270 top
U20 "MCP2562FD" ICC_SO8_5X4_P127 53.775,18.725 r180 top value=MCP2562FDT-H/SN
U21 "MCP2562FD" ICC_SO8_5X4_P127 61.775,18.725 r180 top value=MCP2562FDT-H/SN
U22 "MCP2562FD" ICC_SO8_5X4_P127 70.275,18.725 r180 top value=MCP2562FDT-H/SN
U23 "STMPS2151STR" MOS_SOT23-5L 110.861,13.114 r90 top
U24 "STMPS2151STR" MOS_SOT23-5L 92.025,12.9 r270 top
U25 "USBLC6-4SC6" ESD_SOT23-6L 83.9,8.1 r90 top
U26 "ESD-TRANSIL-DUAL-BIDIR" DIO_SOT323 53.85,7.15 r0 top value=ESDCAN05-2BWY
U27 "ESD-TRANSIL-DUAL-BIDIR" DIO_SOT323 62.1,7.15 r0 top value=ESDCAN05-2BWY
U28 "ESD-TRANSIL-DUAL-BIDIR" DIO_SOT323 70.85,7.15 r0 top value=ESDCAN05-2BWY
U29 "ECMF02-2AMX6" ESD_QFN-6L_1P7X1P5_P050 114.186,7.314 r180 top
U30 "ESD-TRANSIL" ESD_QFN2_1P6X1_P125 111.336,7.339 r90 top value=ESDA7P60-1U1M
U31 "ESD-TRANSIL" ESD_QFN2_1P6X1_P125 147.5,66.375 r90 bottom value=ESDA7P60-1U1M
U32 "ESD-TRANSIL" ESD_QFN2_1P6X1_P125 147.325,52 r180 bottom value=ESDA7P60-1U1M
U33 "MP34DT01TR-M" MIC_HCLGA_3X4X1_4LD 38.399,4.523 r90 bottom value=IMP34DT05TR
U34 "ESD-TRANSIL" ESD_ST0201 9.975,24.075 r0 top value=ESDALC6V1-1U2
X1 "OSCILLATOR_4_PINS" OSC_NDK_NZ2520SB_4P 79.475,61.675 r90 top value=25MHz
X2 "XTAL_2_PINS" CRY_NX3215SA_2P 79.925,54.25 r270 top value=32.768KHz
X3 "OSCILLATOR_4_PINS" OSC_NDK_NZ2520SB_4P 112.786,18.589 r0 top value=25MHz

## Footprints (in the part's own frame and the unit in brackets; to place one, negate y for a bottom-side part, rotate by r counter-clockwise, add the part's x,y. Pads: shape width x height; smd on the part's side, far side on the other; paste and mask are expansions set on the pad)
BRF_VISHAY_DFS_DF01S [mm]
  rect 1.5x1.9 smd mask+0.05: 1(-2.55,-4.39) 2(2.55,-4.39) 3(2.55,4.39) 4(-2.55,4.39)
  silkscreen extent -4.36,-4.5 4.36,4.72, body extent -4.25,-5.15 4.26,5.15, height 3.57
C0402 [mm]
  rect 0.51x0.56 smd mask+0.05: 1(-0.45,0) 2(0.45,0)
  silkscreen extent 0,-0.3 0,0.3, body extent -0.5,-0.3 0.5,0.3, height 0.4
C0603 [mm]
  rect 0.64x0.89 smd mask+0.05: 1(-0.7,0) 2(0.7,0)
  silkscreen extent -1.05,-0.55 1.02,0.55, body extent -0.9,-0.5 0.9,0.5, height 1.4
C0805 [mm]
  rect 0.9x1.4 smd mask+0.05: 1(-0.85,0) 2(0.85,0)
  silkscreen extent -1.3,-0.77 1.3,0.77, body extent -1.1,-0.7 1.1,0.7, height 1.35
C1206_H1P6 [mm]
  rect 1.4x1.78 smd mask+0.05: 1(-1.4,0) 2(1.4,0)
  silkscreen extent -2.12,-0.97 2.15,0.97, body extent -1.7,-0.9 1.7,0.9, height 1.8
C1206_H1P15 [mm]
  rect 1.4x1.78 smd mask+0.05: 1(-1.4,0) 2(1.4,0)
  silkscreen extent -2.12,-0.97 2.15,0.97, body extent -1.7,-0.9 1.7,0.9, height 1.35
C1210 [mm]
  rect 1.4x2.6 smd mask+0.05: 1(-1.4,0) 2(1.4,0)
  silkscreen extent -2.1,-1.43 2.1,1.43, body extent -1.75,-1.35 1.75,1.35, height 2.5
CON_988-JIUBABA_PHFS25-11-02-G0B115-T-1 [mm]
  rect 1.6x1.6 hole 1 mask+0.05: 1(1.27,0)
  round 1.6 hole 1 mask+0.05: 2(-1.27,0)
  silkscreen extent -2.71,-1.33 2.71,1.33, body extent -2.71,-1.33 2.71,1.33, height 8.85
CON_988-JIUBABA_PHFS25-12-10-G0B115-T-1 [mm]
  rect 1.7x1.7 hole 1.1 mask+0.05: 1(-5.08,-1.27)
  round 1.7 hole 1.1 mask+0.05: 2(-5.08,1.27) 3(-2.54,-1.27) 4(-2.54,1.27) 5(0,-1.27) 6(0,1.27) 7(2.54,-1.27) 8(2.54,1.27) 9(5.08,-1.27) 10(5.08,1.27)
  silkscreen extent -6.6,-2.6 6.6,2.6, body extent -6.6,-2.6 6.6,2.6, height 8.85
CON_FCI_20021311-XXX20XXLF [mm]
  rect 1x1 / inner round 1 / far side rect 1x1 hole 0.7 mask+0.05: 1(5.715,0.635)
  round 1 hole 0.7 mask+0.05: 2(5.715,-0.635) 3(4.445,0.635) 4(4.445,-0.635) 5(3.175,0.635) 6(3.175,-0.635) 7(1.905,0.635) 8(1.905,-0.635) 9(0.635,0.635) 10(0.635,-0.635) 11(-0.635,0.635) 12(-0.635,-0.635) 13(-1.905,0.635) 14(-1.905,-0.635) 15(-3.175,0.635) 16(-3.175,-0.635) 17(-4.445,0.635) 18(-4.445,-0.635) 19(-5.715,0.635) 20(-5.715,-0.635)
  silkscreen extent -6.58,-1.5 6.58,1.5, body extent -6.58,-1.5 6.58,1.5, height 4.4
CON_MICROSD_YAMAICHI_PJS008-2003-1 [mm] "WITH POSITIONNING PINS"
  rect 1.6x0.8 smd paste+0 mask+0.05: 1(-15.6,-2.525) 2(-15.6,-1.425) 3(-15.6,-0.325) 4(-15.6,0.775) 5(-15.6,1.875) 6(-15.6,2.975) 7(-15.6,4.075) 8(-15.6,5.175) 9(-15.6,6.325)
  rect 1.4x1.95 smd paste+0 mask+0.05: 10(-5.4,7.225)
  rect 3.5x1.5 smd paste+0 mask+0.05: 11(-2.45,7.45)
  rect 3.5x1.4 smd paste+0 mask+0.05: 12(-2.45,-7.5)
  rect 3.5x1.6 smd paste+0 mask+0.05: 13(-13.45,-7.4)
  rect 3.1x1.2 smd paste+0 mask+0.05: 14(-13.95,7.6)
  round 0 hole 0.65 unplated mask+0.05: NPTH1(-9.8,-4)
  round 0 hole 0.7 unplated mask+0.05: NPTH2(-9.8,3.55)
  silkscreen extent -15.32,-7.25 5.65,7.25, body extent -15.25,-7.25 -0.45,7.42, height 2
CON_PHONE-JACK-3P5_HY_PJ3028B [mm]
  rect 1.5x2.5 smd mask+0.05: 2(1.25,-3.45) 7(2.85,3.45)
  rect 2x2.5 smd mask+0.05: 3(4,-3.45) 4(5.8,3.45) 6(13.2,-3.45)
  rect 2.5x2 smd mask+0.05: 5(17.25,0.75)
  round 0.5 hole 2 unplated mask+0.1: MT1(5,0) MT2(12,0)
  Multi-Layer keep-out circle w0.01: c5,0 r1.25
  Multi-Layer keep-out circle w0.01: c12,0 r1.25
  silkscreen extent -0.9,-3.7 16,3, body extent -0.9,-3 16,3, height 5
CON_RJ45_DGKYD_KRJ-CB4.2GYZNL [mm] "RJ45  connector, right angle"
  rect 1x1 hole 0.7 mask+0.05: 1(3.57,10.6)
  round 1 hole 0.7 mask+0.05: 2(2.55,11.7) 3(1.53,10.6) 4(0.51,11.7) 5(-0.51,10.6) 6(-1.53,11.7) 7(-2.55,10.6) 8(-3.57,11.7) 9(7.06,9.52) 10(4.77,9.52) 11(-4.77,9.52) 12(-7.06,9.52)
  oval 1.3x2.8 hole 0.7 slot 2.2 at 90 deg mask+0.05: SH1(8.04,4.2) SH2(-8.04,4.2)
  Multi-Layer keep-out lines w0.1: 9,0 7,0 7,6.4 ccw(c7,7.3) 7,8.2 -7,8.2 ccw(c-7,7.3) -7,6.4 -7,0 -9,0
  silkscreen extent -8.23,-4.1 8.22,11.45, body extent -8.39,-4.1 8.39,11.9, height 6.85
CON_SAMTEC_SMA-J-P-X-ST-EM1 [mm]
  rect 1.27x3.6 smd mask+0.05: 1(0,1.9)
  rect 1.35x4.2 smd mask+0.05: 2(-2.825,2.1) 3(2.825,2.1)
  rect 1.35x4.2 smd far side mask+0.05: 4(2.825,2.1) 5(-2.825,2.1)
  silkscreen extent -3.62,0 3.62,4.33, body extent -3.17,-9.53 3.18,3.8, height 3.55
